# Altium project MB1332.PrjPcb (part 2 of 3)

## Sheet Peripherals.SchDoc: Peripherals
size A4; Date: Not used; ApprovedBy: Not used; CheckedBy: Not used; Author: Not used; CompanyName: STMicroelectronics; DrawnBy: Not used; Engineer: Not used; Organization: Not used; Address1: Not used; Address2: Not used; Address3: Not used; Address4: Not used; DocumentNumber: Not used; Revision: Not used; SheetNumber: 13; SheetTotal: 17
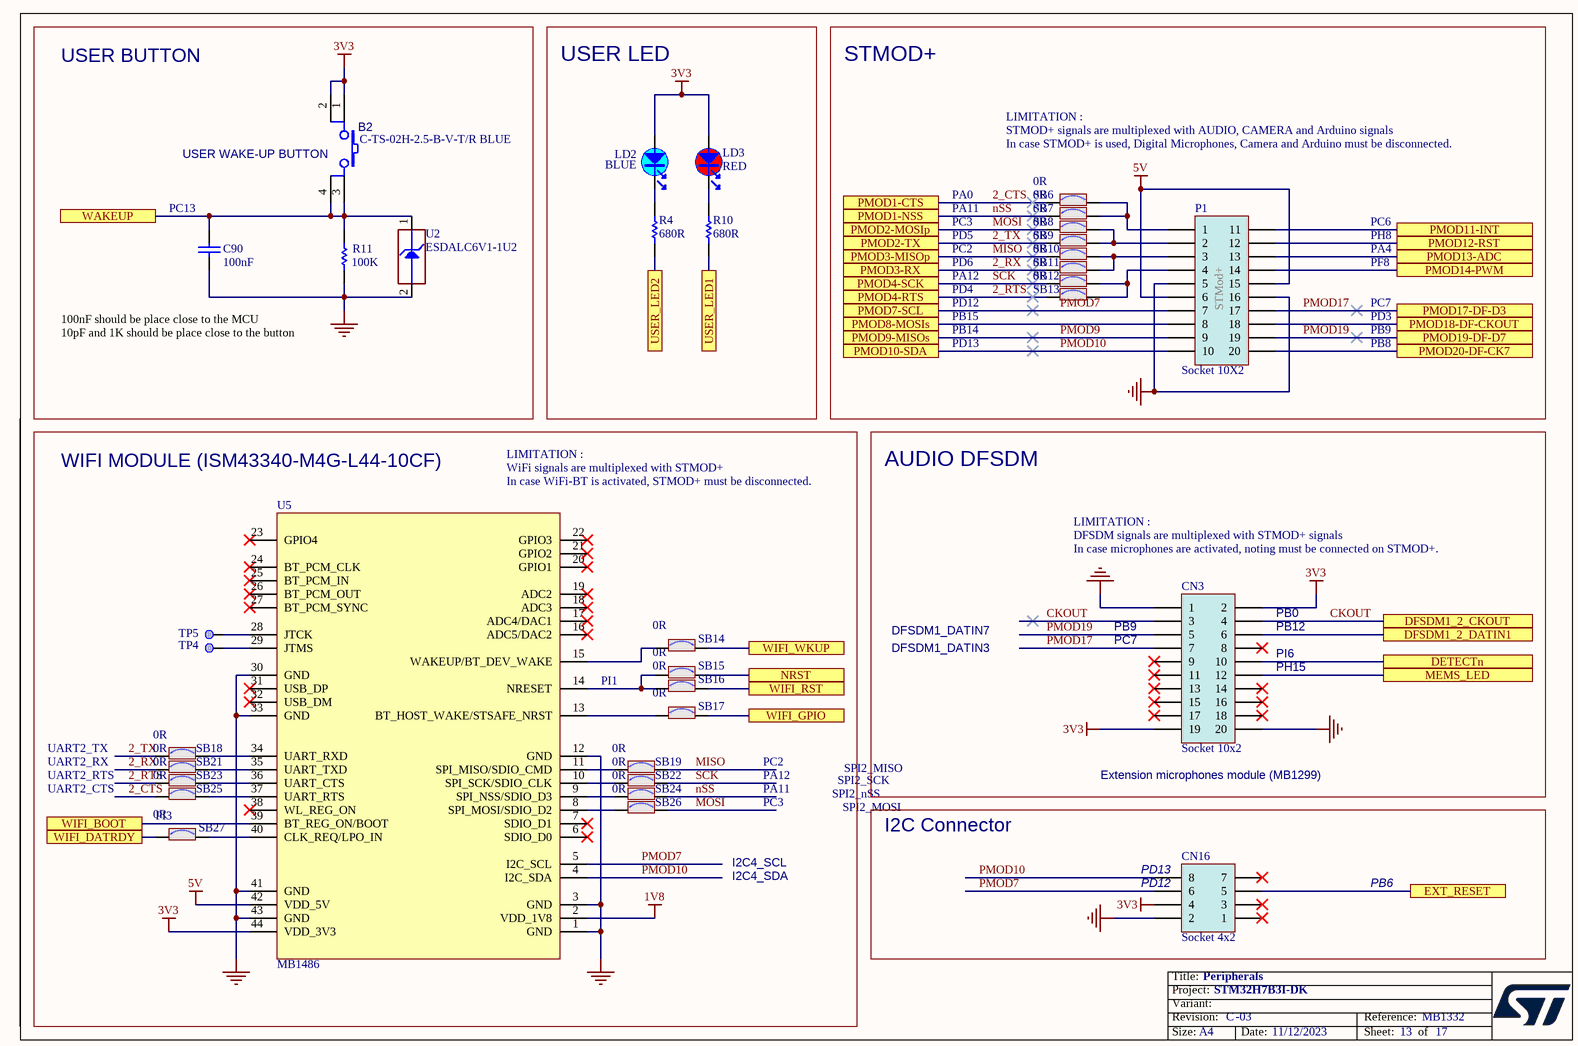
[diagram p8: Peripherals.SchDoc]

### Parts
B2  value C-TS-02H-2.5-B-V-T/R BLUE  [SWI_JIUBABA_C-TS-02H-2-5-B-V-T_R_BLUE]  (hidden comment: SW-PUSH-TS-02H-Blue)
C90  value 100nF  [C0402]  (hidden comment: Capacitor)
CN3  Socket 10x2  [CON_FCI_20021311-XXX20XXLF]
CN16  Socket 4x2  [CON_SAMTEC_SSM-104-L-DH]
LD2  value BLUE  [LED_0603_OSRAM_LB-Q39G-L2OO-35-1_BLUE_1A2K_H0P4]  (hidden comment: LED_blue)
LD3  value RED  [LED_0603_VISHAY_VLMS1300-GS08_RED_1A2K_H0P8]  (hidden comment: LED_red)
P1  value Socket 10X2  [CON_SAMTEC_SQT-110-01-F-D-RA__STMOD+]  (hidden comment: Socket 10X2 STMod+)
R4  value 680R  [R0603]  (hidden comment: Resistor)
R10  value 680R  [R0603]  (hidden comment: Resistor)
R11  value 100K  [R0402]  (hidden comment: Resistor)
SB6  value 0R  [SOLDER-BRIDGE_R0603-0R]  (hidden comment: SB_ON)
SB7  value 0R  [SOLDER-BRIDGE_R0603-0R]  (hidden comment: SB_ON)
SB8  value 0R  [SOLDER-BRIDGE_R0603-0R]  (hidden comment: SB_ON)
SB9  value 0R  [SOLDER-BRIDGE_R0603-0R]  (hidden comment: SB_ON)
SB10  value 0R  [SOLDER-BRIDGE_R0603-0R]  (hidden comment: SB_ON)
SB11  value 0R  [SOLDER-BRIDGE_R0603-0R]  (hidden comment: SB_ON)
SB12  value 0R  [SOLDER-BRIDGE_R0603-0R]  (hidden comment: SB_ON)
SB13  value 0R  [SOLDER-BRIDGE_R0603-0R]  (hidden comment: SB_ON)
SB14  value 0R  [SOLDER-BRIDGE_R0603-0R]  (hidden comment: SB_ON)
SB15  value 0R  [SOLDER-BRIDGE_R0603-0R]  (hidden comment: SB_ON)
SB16  value 0R  [SOLDER-BRIDGE_R0603-0R]  (hidden comment: SB_ON)
SB17  value 0R  [SOLDER-BRIDGE_R0603-0R]  (hidden comment: SB_ON)
SB18  value 0R  [SOLDER-BRIDGE_R0603-0R]  (hidden comment: SB_ON)
SB19  value 0R  [SOLDER-BRIDGE_R0603-0R]  (hidden comment: SB_ON)
SB21  value 0R  [SOLDER-BRIDGE_R0603-0R]  (hidden comment: SB_ON)
SB22  value 0R  [SOLDER-BRIDGE_R0603-0R]  (hidden comment: SB_ON)
SB23  value 0R  [SOLDER-BRIDGE_R0603-0R]  (hidden comment: SB_ON)
SB24  value 0R  [SOLDER-BRIDGE_R0603-0R]  (hidden comment: SB_ON)
SB25  value 0R  [SOLDER-BRIDGE_R0603-0R]  (hidden comment: SB_ON)
SB26  value 0R  [SOLDER-BRIDGE_R0603-0R]  (hidden comment: SB_ON)
SB27  value 0R  [SOLDER-BRIDGE_R0603-0R]  (hidden comment: SB_ON)
TP4  Test Point  [TP_SMD_0-6MM]  (value not drawn)  (no BOM)
TP5  Test Point  [TP_SMD_0-6MM]  (value not drawn)  (no BOM)
U2  value ESDALC6V1-1U2  [ESD_ST0201]  (hidden comment: ESD-TRANSIL)
U5  value MB1486  [MOD_WIFI_INVENTEK_ISM43362]  (hidden comment: WIFI MODULE INTERPOSER)

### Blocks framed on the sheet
USER BUTTON: B2 C90 R11 U2
USER LED: LD2 LD3 R4 R10
STMOD+: P1 SB6-SB13
WIFI MODULE (ISM43340-M4G-L44-10CF): SB14-SB19 SB21-SB27 TP4 TP5 U5
AUDIO DFSDM: CN3
I2C Connector: CN16

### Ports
DETECTn, DFSDM1_2_CKOUT, DFSDM1_2_DATIN1, EXT_RESET, MEMS_LED, NRST, PMOD1-CTS, PMOD1-NSS, PMOD2-MOSIp, PMOD2-TX, PMOD3-MISOp, PMOD3-RX, PMOD4-RTS, PMOD4-SCK, PMOD7-SCL, PMOD8-MOSIs, PMOD9-MISOs, PMOD10-SDA, PMOD11-INT, PMOD12-RST, PMOD13-ADC, PMOD14-PWM, PMOD17-DF-D3, PMOD18-DF-CKOUT, PMOD19-DF-D7, PMOD20-DF-CK7, USER_LED1, USER_LED2, WAKEUP, WIFI_BOOT, WIFI_DATRDY, WIFI_GPIO, WIFI_RST, WIFI_WKUP

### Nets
1V8: U5.2(VDD_1V8)
3V3: B2.1 B2.2 CN3.2 CN3.19 CN16.4 LD2.1 LD3.1 U5.44(VDD_3V3)
5V: P1.6 P1.15 U5.42(VDD_5V)
GND: C90.1 CN3.1 CN3.20 CN16.2 P1.5 P1.16 R11.1 U2.2(GND) U5.1(GND) U5.3(GND) U5.12(GND) U5.30(GND) U5.33(GND) U5.41(GND) U5.43(GND)
2_CTS: SB6.1 SB25.2 ; port PMOD1-CTS
2_RTS: SB13.1 SB23.2 ; port PMOD4-RTS
2_RX: SB11.1 SB21.2 ; port PMOD3-RX
2_TX: SB9.1 SB18.2 ; port PMOD2-TX
CKOUT: CN3.3 CN3.4 ; port DFSDM1_2_CKOUT
DCMI_D0: P1.11 ; port PMOD11-INT
DCMI_D5: P1.18 ; port PMOD18-DF-CKOUT
DCMI_D6: P1.20 ; port PMOD20-DF-CK7
DETECTn: CN3.10 ; port DETECTn
DFSDM1_2_DATIN1: CN3.6 ; port DFSDM1_2_DATIN1
EXT_RESET: CN16.5 ; port EXT_RESET
MEMS_LED: CN3.12 ; port MEMS_LED
MISO: SB10.1 SB19.1 ; port PMOD3-MISOp
MOSI: SB8.1 SB26.1 ; port PMOD2-MOSIp
nSS: SB7.1 SB24.1 ; port PMOD1-NSS
PH8: P1.12 ; port PMOD12-RST
PMOD7: CN16.6 P1.7 U5.5(I2C_SCL) ; port PMOD7-SCL
PMOD8-MOSIs: P1.8 ; port PMOD8-MOSIs
PMOD9: P1.9 ; port PMOD9-MISOs
PMOD10: CN16.8 P1.10 U5.4(I2C_SDA) ; port PMOD10-SDA
PMOD13-ADC: P1.13 ; port PMOD13-ADC
PMOD14-PWM: P1.14 ; port PMOD14-PWM
PMOD17: CN3.7 P1.17 ; port PMOD17-DF-D3  [project net DCMI_D1]
PMOD19: CN3.5 P1.19 ; port PMOD19-DF-D7  [project net DCMI_D7]
SCK: SB12.1 SB22.1 ; port PMOD4-SCK  [project net PA12]
T_NRST: SB15.2 ; port NRST
USER_LED1: R10.2 ; port USER_LED1
USER_LED2: R4.2 ; port USER_LED2
WAKEUP: B2.3 B2.4 C90.2 R11.2 U2.1(IO1) ; port WAKEUP
WIFI_BOOT: U5.39(BT_REG_ON/BOOT) ; port WIFI_BOOT
WIFI_DATRDY: SB27.1 ; port WIFI_DATRDY
WIFI_GPIO: SB17.2 ; port WIFI_GPIO
WIFI_RST: SB16.2 ; port WIFI_RST
WIFI_WKUP: SB14.2 ; port WIFI_WKUP
NetLD2_2: LD2.2 R4.1
NetLD3_2: LD3.2 R10.1
NetP1_1: P1.1 SB6.2 SB7.2
NetP1_2: P1.2 SB8.2 SB9.2
NetP1_3: P1.3 SB10.2 SB11.2
NetP1_4: P1.4 SB12.2 SB13.2
NetSB14_1: SB14.1 U5.15(WAKEUP/BT_DEV_WAKE)
NetSB15_1: SB15.1 SB16.1 U5.14(NRESET)
NetSB17_1: SB17.1 U5.13(BT_HOST_WAKE/STSAFE_NRST)
NetSB18_1: SB18.1 U5.34(UART_RXD)
NetSB19_2: SB19.2 U5.11(SPI_MISO/SDIO_CMD)
NetSB21_1: SB21.1 U5.35(UART_TXD)
NetSB22_2: SB22.2 U5.10(SPI_SCK/SDIO_CLK)
NetSB23_1: SB23.1 U5.36(UART_CTS)
NetSB24_2: SB24.2 U5.9(SPI_NSS/SDIO_D3)
NetSB25_1: SB25.1 U5.37(UART_RTS)
NetSB26_2: SB26.2 U5.8(SPI_MOSI/SDIO_D2)
NetSB27_2: SB27.2 U5.40(CLK_REQ/LPO_IN)
NetTP4_1: TP4.1 U5.29(JTMS)
NetTP5_1: TP5.1 U5.28(JTCK)

Not connected (* = marked no-connect by the designer): CN3 8* 9* 11* 13* 14* 15* 16* 17* 18*; CN16 1* 3* 7*; U5 6(SDIO_D0)* 7(SDIO_D1)* 16(ADC5/DAC2)* 17(ADC4/DAC1)* 18(ADC3)* 19(ADC2)* 20(GPIO1)* 21(GPIO2)* 22(GPIO3)* 23(GPIO4)* 24(BT_PCM_CLK)* 25(BT_PCM_IN)* 26(BT_PCM_OUT)* 27(BT_PCM_SYNC)* 31(USB_DP)* 32(USB_DM)* 38(WL_REG_ON)*

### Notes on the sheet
- (near B2) USER WAKE-UP BUTTON
- LIMITATION :
  STMOD+ signals are multiplexed with AUDIO, CAMERA and Arduino signals
  In case STMOD+ is used, Digital Microphones, Camera and Arduino must be disconnected.
- (near C90) PC13
- PA0
- PC3
- PD5
- PC2
- PA11
- PC6
- PH8
- PA4
- PD6
- PA12
- PD12
- PB15
- PD4
- PF8
- PC7
- PD3
- 100nF should be place close to the MCU
  10pF and 1K should be place close to the button
- PD13
- PB14
- PB9
- PB8
- LIMITATION :
  WiFi signals are multiplexed with STMOD+
  In case WiFi-BT is activated, STMOD+ must be disconnected.
- DFSDM1_DATIN3
- DFSDM1_DATIN7
- (near CN3) LIMITATION :
  DFSDM signals are multiplexed with STMOD+ signals
  In case microphones are activated, noting must be connected on STMOD+.
- (near CN3) PB9
- (near CN3) PC7
- (near CN3) PB0
- (near CN3) PB12
- (near CN3) PI6
- PI1
- (near CN3) PH15
- UART2_TX
- UART2_RX
- UART2_RTS
- UART2_CTS
- SPI2_nSS
- SPI2_SCK
- SPI2_MISO
- (near CN3) Extension microphones module (MB1299)
- PI3
- SPI2_MOSI
- I2C4_SCL
- I2C4_SDA
- (near CN16) PD13
- (near CN16) PD12
- PB6

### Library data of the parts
B2 = MCD-00172: Switch HW SMD blue; Part_Type: Misc; Manufacturer: JIUBABA; Part_Preference: Alternate; Provided_By: SUBCO; Alternate_EMS: A; Component_Country_Of_Origin: Unknown; ID: 2697; ShowFields: YES
C90 = MCD-00006: Capacitor, MLCC, 100nF, 16V, X7R, +/-10%, 0402, T=0.5mm; Manufacturer_Part_Number: CC0402KRX7R7BB104; Manufacturer: YAGEO; Part_Preference: Recommended; Partial_Alternate_Internal_Part_Number: MCD-03299; Component_Country_Of_Origin: China; ID: 2474; Order_Code_RS: 9402047; ShowFields: YES
CN3 = MCD-00147: Socket for MB1299, 10x2, 1.27mm, VR, TH, Height 4.30mm/2.40mm; Part_Type: Connector; Manufacturer_Part_Number: 20021311-00020T4LF; Manufacturer: AMPHENOL ICC; Alternate_Manufacturer_Part_Number: 234220S1410; Alternate_Manufacturer: JIUBABA; Part_Preference: Recommended; Partial_Alternate_Internal_Part_Number: MCD-03007; Provided_By: SUBCO; Component_Country_Of_Origin: China; ID: 2719; Order_Code_RS: 170-8859; ShowFields: YES
CN16 = MCD-00131: Socket, 4x2, 2.54mm, RA, SMT, Height 5.72mm; Manufacturer_Part_Number: SSM-104-L-DH; Manufacturer: SAMTEC; Part_Type: Connector; Alternate_Manufacturer_Part_Number: F206A-2x04MGF-LA; Alternate_Manufacturer: JIUBABA; Part_Preference: Recommended; Provided_By: SUBCO; Component_Country_Of_Origin: China, Costa Rica, Malaysia, United States, Vietnam; ID: 2740; Order_Code_RS: 198-1510; ShowFields: YES
LD2 = MCD-00585: LED Blue, 0603 SMD, Forward Voltage Min=2,8V, Max=3,8V; Manufacturer_Part_Number: LB Q39G-L2OO-35-1; Manufacturer: OSRAM OPTO SEMICONDUCTORS; Part_Type: Display; Alternate_Manufacturer_Part_Number: 19-217-BHC-ZL1M2RY-3T-V4; Alternate_Manufacturer: EVERLIGHT; Full_Alternate_Internal_Part_Number: MCD-02398; Part_Preference: Recommended; Order_Code_RS: 9148643; Provided_By: SUBCO; Component_Country_Of_Origin: Unknown; ID: 3159; ShowFields: YES
LD3 = MCD-00587: LED Red, 0603 SMD, 2V Forward Voltage; Manufacturer_Part_Number: VLMS1300-GS08; Manufacturer: VISHAY; Alternate_Manufacturer_Part_Number: LS Q976-NR-1; Alternate_Manufacturer: OSRAM OPTO SEMICONDUCTORS; Part_Type: Display; Full_Alternate_Internal_Part_Number: MCD-02401; Part_Preference: Recommended; Provided_By: SUBCO; Component_Country_Of_Origin: China; ID: 3154; ShowFields: YES
P1 = MCD-00309: Socket 10x2, 2.00mm, RA, TH, Height 6.35mm/2.29mm; Part_Type: Connector; Manufacturer_Part_Number: SQT-110-01-F-D-RA; Manufacturer: SAMTEC; Alternate_Manufacturer_Part_Number: FH200020C-12300; Alternate_Manufacturer: JIUBABA; Part_Preference: Recommended; Provided_By: SUBCO; Component_Country_Of_Origin: China, Costa Rica, Malaysia, United States, Vietnam; ID: 2557; Order_Code_RS: 180-1541; ShowFields: YES
R4 R10 = MCD-00508: Resistor,680R,0603,1%,1/10W; Manufacturer_Part_Number: RC0603FR-07680RL; Manufacturer: YAGEO; Part_Preference: Recommended; Provided_By: SUBCO; Component_Country_Of_Origin: China; ID: 3235; ShowFields: YES
R11 = MCD-00059: Resistor,100K,0402,1%,1/16W; Manufacturer_Part_Number: RC0402FR-07100KL; Manufacturer: YAGEO; Alternate_Manufacturer_Part_Number: RT0402FRE07100KL; Part_Preference: Recommended; Partial_Alternate_Internal_Part_Number: MCD-03301; Provided_By: SUBCO; Component_Country_Of_Origin: China; ID: 2533; Order_Code_RS: 2421891; ShowFields: YES
SB6-SB19 SB21-SB27 = MCD-00071: Solder Bridge ON; Part_Type: Resistor; Manufacturer_Part_Number: RC0603JR-070RL; Manufacturer: YAGEO; Manufacturer_HQ_COO: Unknown; Part_Preference: Recommended; Provided_By: SUBCO; Component_Country_Of_Origin: China; ID: 2521; Order_Code_RS: 199-5647; ShowFields: YES
TP4 TP5 = MCD-00631: Test Point 0.6mm; Part_Type: Misc; Part_Preference: Recommended; ID: 3108; ShowFields: YES
U2 = MCD-00170: ESD protection 6V1; Part_Type: Diode; Manufacturer: STMICROELECTRONICS; BMS_Part_Number: 9151132; Manufacturer_HQ_COO: EU; Part_Preference: Recommended; Provided_By: SUBCO with ST control; Component_Country_Of_Origin: China; ID: 2696; Order_Code_RS: 795-8404; ShowFields: YES
U5 = MCD-01999: 44 pins Interposer for WIFI module (MB1486 module is with INVENTEK ISM43340-M4G-L44-10CF); Part_Type: Misc; Manufacturer_Part_Number: MB1486 - WIFI MODULE WITH INVENTEK ISM43340-M4G-L44-10CF; Manufacturer: STMICROELECTRONICS; Manufacturer_HQ_COO: EU; Part_Preference: Recommended; ECCN_US: 5A992C; Provided_By: SUBCO with ST control; Component_Country_Of_Origin: Unknown; ID: 4099; ShowFields: YES

## Sheet SDcard.SchDoc: SD Card
size A4; Date: Not used; ApprovedBy: Not used; CheckedBy: Not used; Author: Not used; CompanyName: STMicroelectronics; DrawnBy: Not used; Engineer: Not used; Organization: Not used; Address1: Not used; Address2: Not used; Address3: Not used; Address4: Not used; DocumentNumber: Not used; Revision: Not used; SheetNumber: 7; SheetTotal: 17
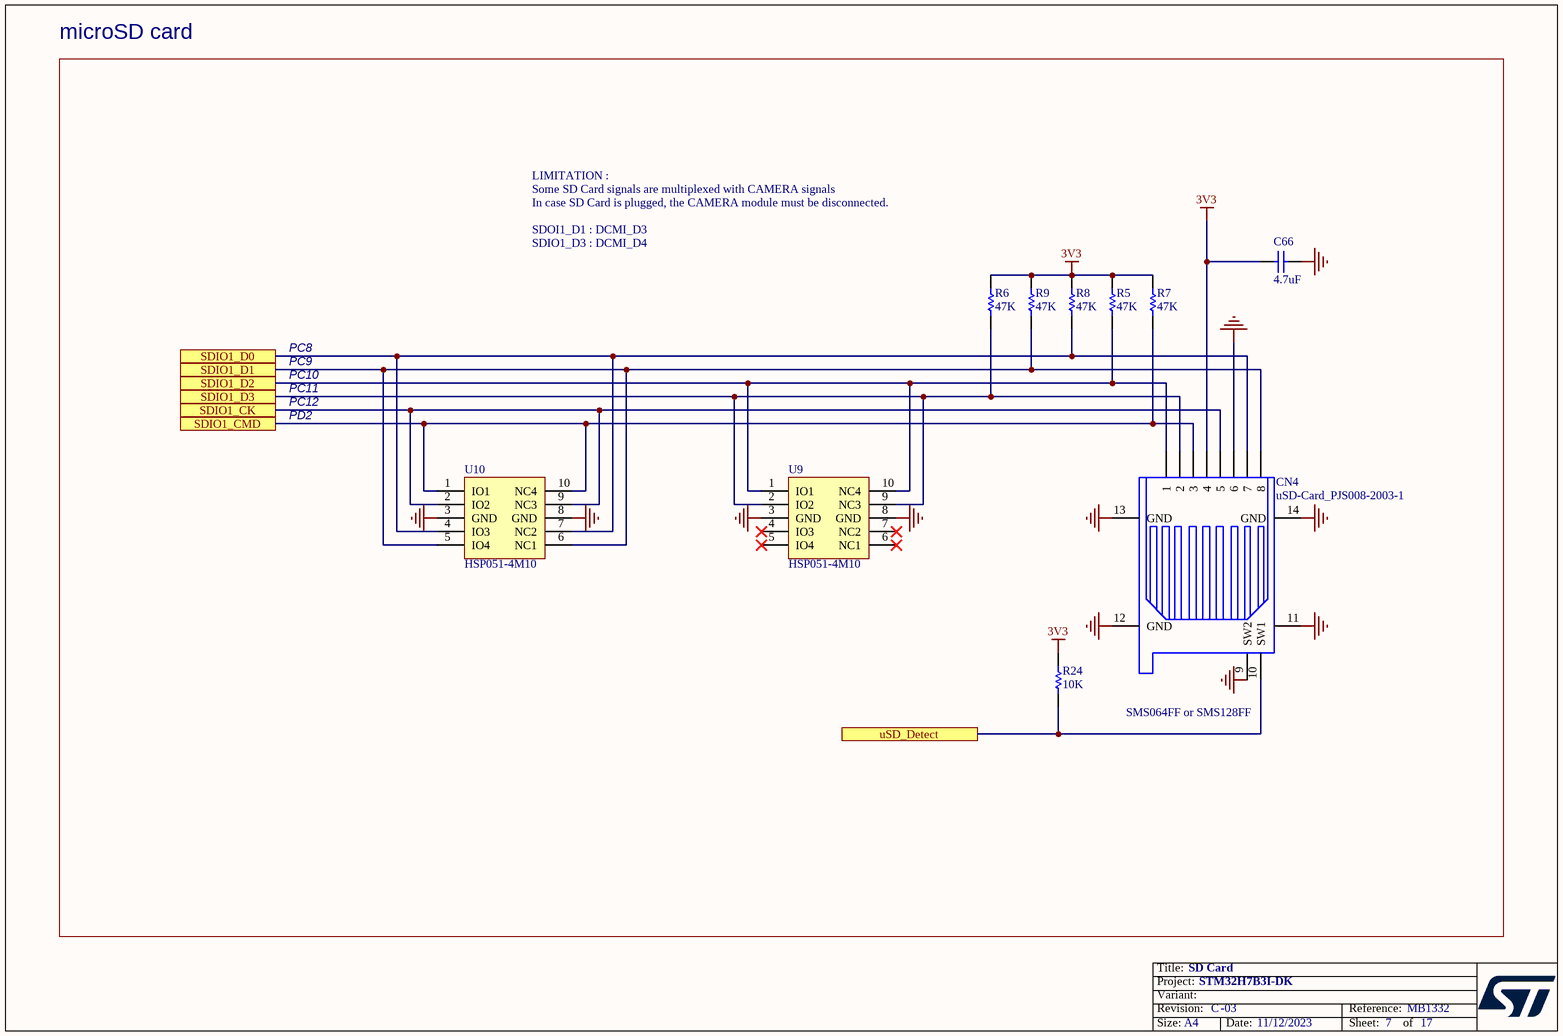
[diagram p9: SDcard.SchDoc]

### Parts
C66  value 4.7uF  [C0603_H0P8]  (hidden comment: Capacitor)
CN4  value uSD-Card_PJS008-2003-1  [CON_MICROSD_YAMAICHI_PJS008-2003-1]  (hidden comment: microSD-PJS008-2003)
R5  value 47K  [R0402]  (hidden comment: Resistor)
R6  value 47K  [R0402]  (hidden comment: Resistor)
R7  value 47K  [R0402]  (hidden comment: Resistor)
R8  value 47K  [R0402]  (hidden comment: Resistor)
R9  value 47K  [R0402]  (hidden comment: Resistor)
R24  value 10K  [R0603]  (hidden comment: Resistor)
U9  HSP051-4M10  [ESD_UQFN-10L_2P5X1_P050]
U10  HSP051-4M10  [ESD_UQFN-10L_2P5X1_P050]

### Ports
SDIO1_CK, SDIO1_CMD, SDIO1_D0, SDIO1_D1, SDIO1_D2, SDIO1_D3, uSD_Detect

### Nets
3V3: C66.1 CN4.4 R5.2 R6.2 R7.2 R8.2 R9.2 R24.2
GND: C66.2 CN4.6 CN4.9(SW2) CN4.11(GND) CN4.12(GND) CN4.13(GND) CN4.14(GND) U9.3(GND) U9.8(GND) U10.3(GND) U10.8(GND)
DCMI_D3: CN4.8 R9.1 U10.5(IO4) U10.6(NC1) ; port SDIO1_D1
DCMI_D4: CN4.2 R6.1 U9.2(IO2) U9.9(NC3) ; port SDIO1_D3
SDIO1_CK: CN4.5 U10.2(IO2) U10.9(NC3) ; port SDIO1_CK
SDIO1_CMD: CN4.3 R7.1 U10.1(IO1) U10.10(NC4) ; port SDIO1_CMD
SDIO1_D0: CN4.7 R8.1 U10.4(IO3) U10.7(NC2) ; port SDIO1_D0
SDIO1_D2: CN4.1 R5.1 U9.1(IO1) U9.10(NC4) ; port SDIO1_D2
uSD_Detect: CN4.10(SW1) R24.1 ; port uSD_Detect

Not connected (* = marked no-connect by the designer): U9 4(IO3)* 5(IO4)* 6(NC1)* 7(NC2)*

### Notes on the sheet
- microSD card
- LIMITATION :
  Some SD Card signals are multiplexed with CAMERA signals
  In case SD Card is plugged, the CAMERA module must be disconnected.
  SDOI1_D1 : DCMI_D3
  SDIO1_D3 : DCMI_D4
- PC8
- PC9
- PC10
- PC11
- PD2
- PC12
- SMS064FF or SMS128FF

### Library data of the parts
C66 = MCD-01721: Capacitor, 4.7uF, 10V, X5R, 10%, 0603, T=0.8mm; Manufacturer_Part_Number: CC0603KRX5R6BB475; Manufacturer: YAGEO; Part_Preference: Recommended; Provided_By: SUBCO; Component_Country_Of_Origin: China; ID: 3821; ShowFields: YES
CN4 = MCD-00023: MicroSD Card Conn, Reversed-Type, Mnt Push-Push, Positionning holes; Manufacturer_Part_Number: PJS008-2003-1; Manufacturer: YAMAICHI; Part_Type: Connector; Part_Preference: Recommended; Provided_By: SUBCO; Component_Country_Of_Origin: Unknown; ID: 2492; ShowFields: YES
R5-R9 = MCD-00063: Resistor,47K,0402,1%,1/16W; Manufacturer_Part_Number: RC0402FR-0747KL; Manufacturer: YAGEO; Part_Preference: Recommended; Provided_By: SUBCO; Component_Country_Of_Origin: China; ID: 2528; Order_Code_RS: 9239430; ShowFields: YES
R24 = MCD-00220: Resistor,10K,0603,1%,1/10W; Manufacturer_Part_Number: RC0603FR-0710KL; Manufacturer: YAGEO; Part_Preference: Recommended; Provided_By: SUBCO; Component_Country_Of_Origin: China; ID: 2649; ShowFields: YES
U9 U10 = MCD-00667: 4-line ESD protection for high speed lines; Part_Type: Diode; Manufacturer: STMICROELECTRONICS; BMS_Part_Number: 9179041; Manufacturer_HQ_COO: EU; Part_Preference: Recommended; Provided_By: SUBCO with ST control; Component_Country_Of_Origin: Philippines; ID: 3081; ShowFields: YES

## Sheet USB_OTG_HS_externalPHY.SchDoc: USB OTG HS with external PHY
size A3; Date: Not used; ApprovedBy: Not used; CheckedBy: Not used; Author: Not used; CompanyName: STMicroelectronics; DrawnBy: Not used; Engineer: Not used; Organization: Not used; Address1: Not used; Address2: Not used; Address3: Not used; Address4: Not used; DocumentNumber: Not used; Revision: Not used; SheetNumber: 4; SheetTotal: 17
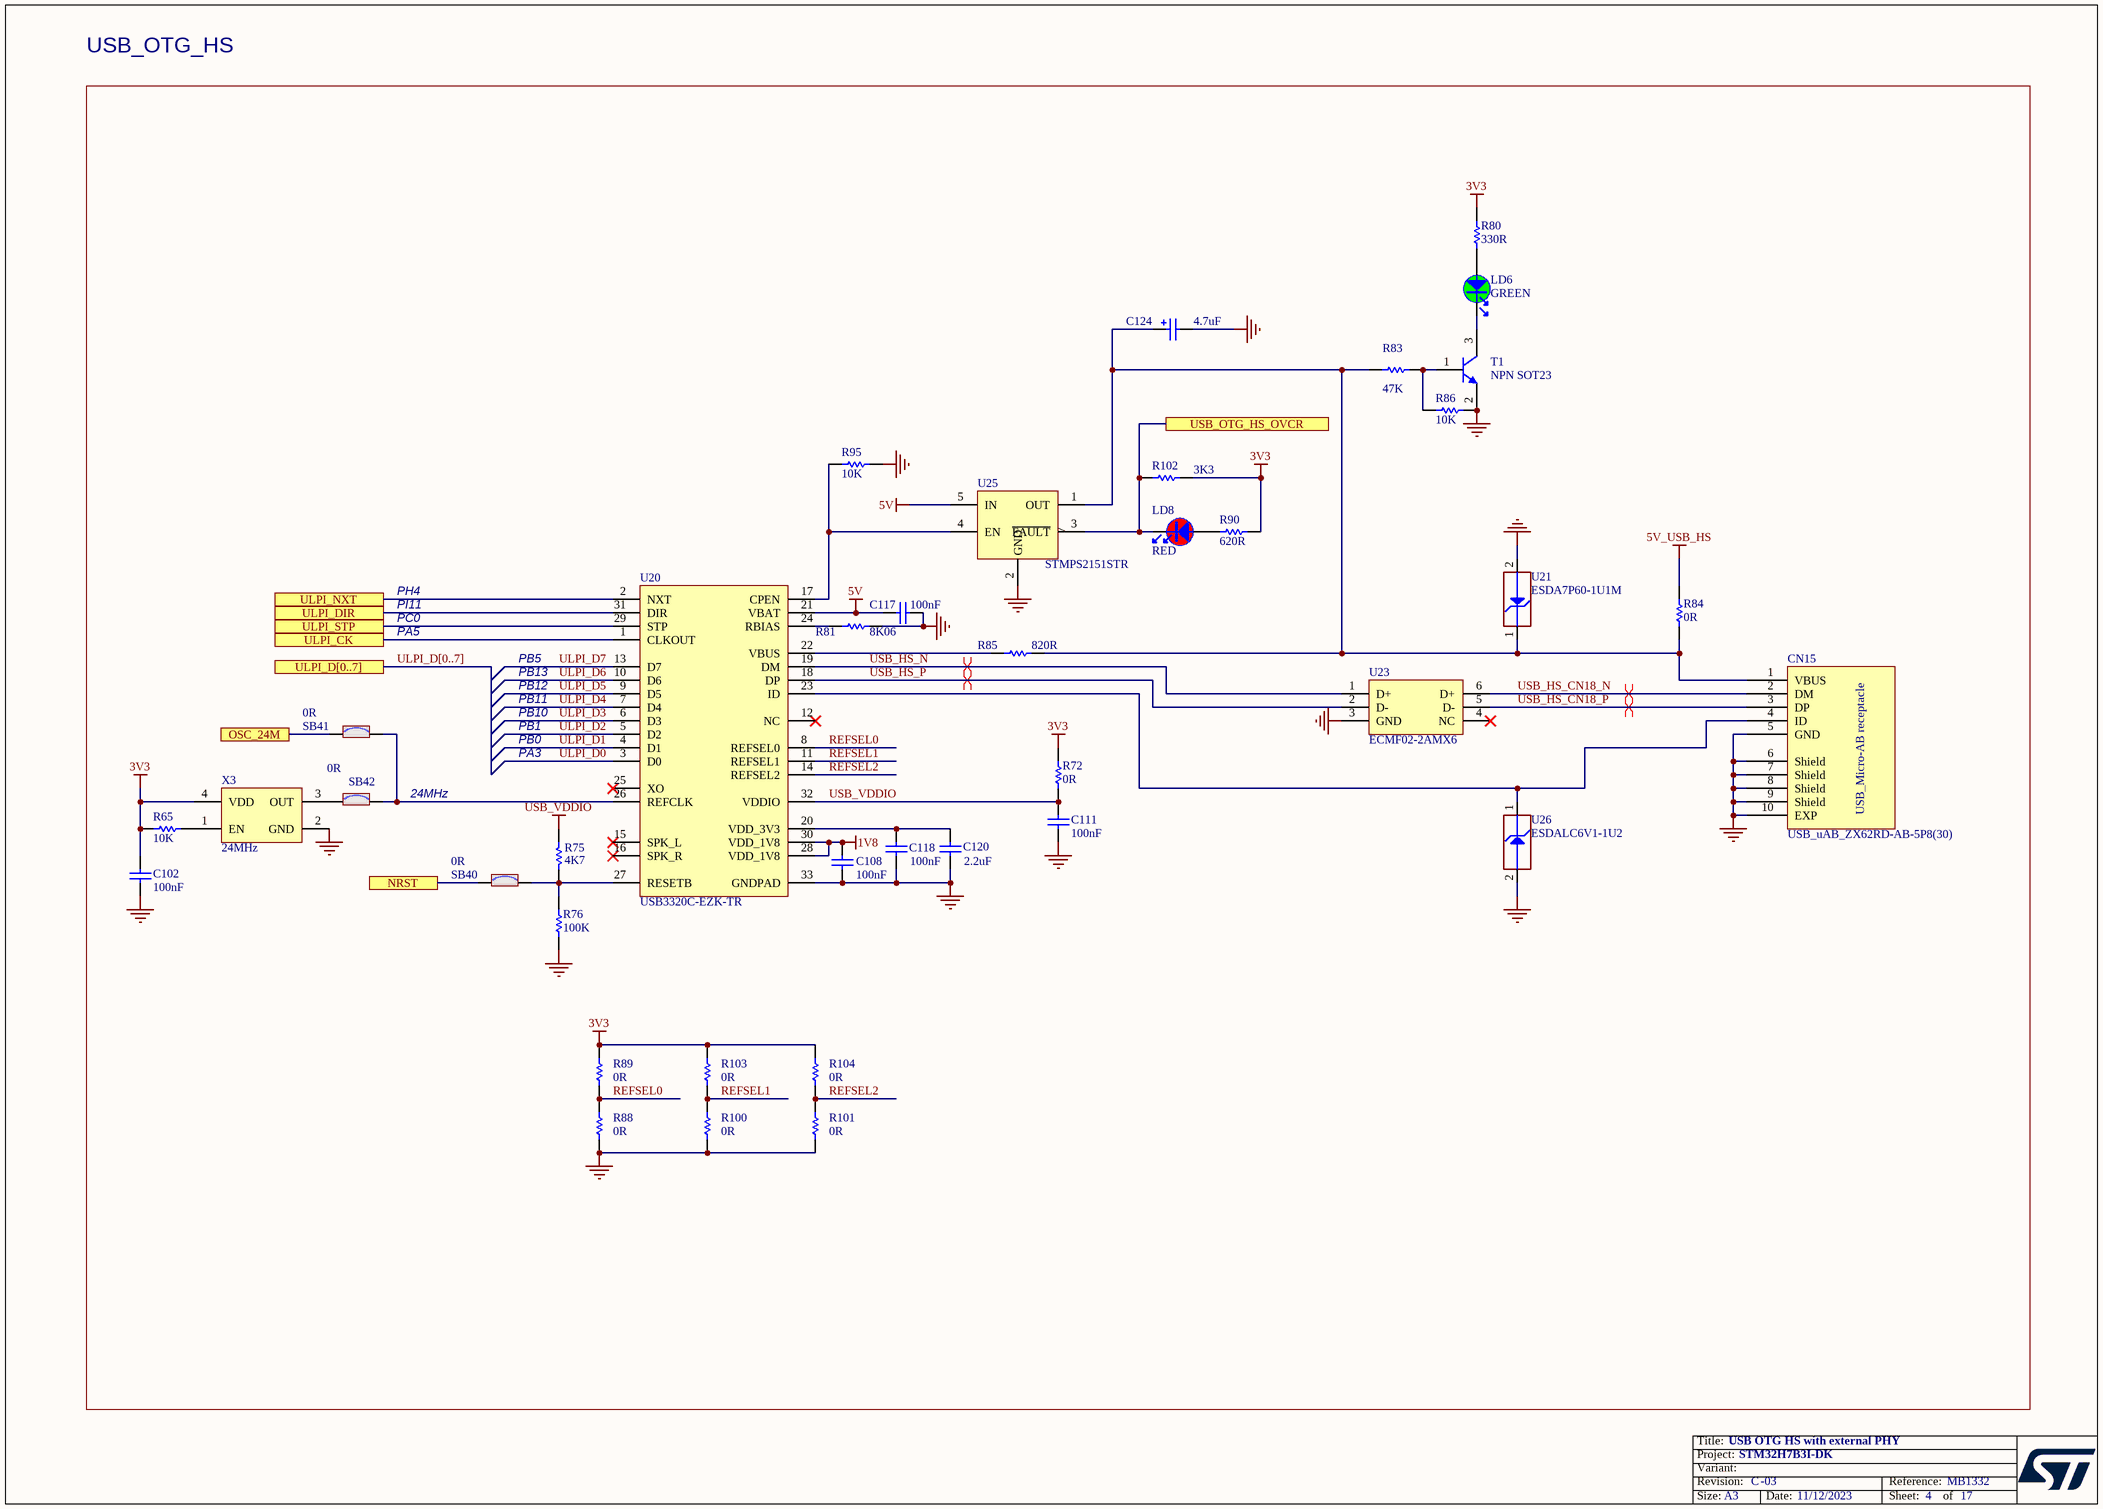
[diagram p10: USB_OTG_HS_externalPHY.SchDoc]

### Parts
C102  value 100nF  [C0402]  (hidden comment: Capacitor)
C108  value 100nF  [C0402]  (hidden comment: Capacitor)
C111  value 100nF  [C0402]  (hidden comment: Capacitor)
C117  value 100nF  [C0402]  (hidden comment: Capacitor)
C118  value 100nF  [C0402]  (hidden comment: Capacitor)
C120  value 2.2uF  [C0603]  (hidden comment: Capacitor)
C124  value 4.7uF  [CPOL_TAJ-A_1206_H180]  (hidden comment: Cap_POL_TANA)
CN15  value USB_uAB_ZX62RD-AB-5P8(30)  [CON_USBMICROAB_MOLEX_47590-0001_H3]  (hidden comment: USB_uAB_47590.0001)
LD6  value GREEN  [LED_0603_OSRAM_LG-Q396-PS-35_GREEN_1A2K_H0P4]  (hidden comment: LED_green)
LD8  value RED  [LED_0603_VISHAY_VLMS1300-GS08_RED_1A2K_H0P8]  (hidden comment: LED_red)
R65  value 10K  [R0402]  (hidden comment: Resistor)
R72  value 0R  [R0603]  (hidden comment: Resistor)
R75  value 4K7  [R0402]  (hidden comment: Resistor)
R76  value 100K  [R0402]  (hidden comment: Resistor)
R80  value 330R  [R0603]  (hidden comment: Resistor)
R81  value 8K06  [R0603]  (hidden comment: Resistor)
R83  value 47K  [R0402]  (hidden comment: Resistor)
R84  value 0R  [R0805]  (hidden comment: Resistor)
R85  value 820R  [R0603]  (hidden comment: Resistor)
R86  value 10K  [R0402]  (hidden comment: Resistor)
R88  value 0R  [R0603]  (hidden comment: Resistor)
R89  value 0R  [R0603]  (hidden comment: Resistor)
R90  value 620R  [R0603]  (hidden comment: Resistor)
R95  value 10K  [R0402]  (hidden comment: Resistor)
R100  value 0R  [R0603]  (hidden comment: Resistor)
R101  value 0R  [R0603]  (hidden comment: Resistor)
R102  value 3K3  [R0402]  (hidden comment: Resistor)
R103  value 0R  [R0603]  (hidden comment: Resistor)
R104  value 0R  [R0603]  (hidden comment: Resistor)
SB40  value 0R  [SOLDER-BRIDGE_R0603-0R]  (hidden comment: SB_ON)
SB41  value 0R  [SOLDER-BRIDGE_R0603-0R]  (hidden comment: SB_ON)
SB42  value 0R  [SOLDER-BRIDGE_R0603-0R]  (hidden comment: SB_ON)
T1  value NPN SOT23  [NPN_SOT23]  (hidden comment: 9013-SOT23)
U20  value USB3320C-EZK-TR  [ICC_QFN32-EPAD_5X5_P050]  (hidden comment: USB3320C-EZK)
U21  value ESDA7P60-1U1M  [ESD_QFN2_1P6X1_P125]  (hidden comment: ESD-TRANSIL)
U23  ECMF02-2AMX6  [ESD_QFN-6L_1P7X1P5_P050]
U25  STMPS2151STR  [MOS_SOT23-5L]
U26  value ESDALC6V1-1U2  [ESD_ST0201]  (hidden comment: ESD-TRANSIL)
X3  value 24MHz  [OSC_NDK_NZ2520SB_4P]  (hidden comment: OSCILLATOR_4_PINS)

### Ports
NRST, OSC_24M, ULPI_CK, ULPI_D[0..7], ULPI_DIR, ULPI_NXT, ULPI_STP, USB_OTG_HS_OVCR

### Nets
1V8: C108.1 U20.28(VDD_1V8) U20.30(VDD_1V8)
3V3: C102.2 R65.1 R72.1 R80.2 R89.2 R90.2 R102.2 R103.2 R104.2 X3.4(VDD)
5V: C117.1 U20.21(VBAT) U25.5(IN)
5V_USB_HS: R84.2
GND: C102.1 C108.2 C111.2 C117.2 C118.2 C120.1 C124.2 CN15.5(GND) CN15.6(Shield) CN15.7(Shield) CN15.8(Shield) CN15.9(Shield) CN15.10(EXP) R76.1 R81.2 R86.2 R88.1 R95.2 R100.1 R101.1 T1.2(E) U20.33(GNDPAD) U21.2(GND) U23.3(GND) U25.2(GND) U26.2(GND) X3.2(GND)
USB_VDDIO: C111.1 R72.2 R75.2 U20.32(VDDIO)
OSC_24M: SB41.2 ; port OSC_24M
REFSEL0: R88.2 R89.1 U20.8(REFSEL0)
REFSEL1: R100.2 R103.1 U20.11(REFSEL1)
REFSEL2: R101.2 R104.1 U20.14(REFSEL2)
T_NRST: SB40.2 ; port NRST
ULPI_CK: U20.1(CLKOUT) ; port ULPI_CK
ULPI_D0: U20.3(D0)
ULPI_D1: U20.4(D1)
ULPI_D2: U20.5(D2)
ULPI_D3: U20.6(D3)
ULPI_D4: U20.7(D4)
ULPI_D5: U20.9(D5)
ULPI_D6: U20.10(D6)
ULPI_D7: U20.13(D7)
ULPI_DIR: U20.31(DIR) ; port ULPI_DIR
ULPI_NXT: U20.2(NXT) ; port ULPI_NXT
ULPI_STP: U20.29(STP) ; port ULPI_STP
USB_HS_CN18_N: CN15.2(DM) U23.6(D+)
USB_HS_CN18_P: CN15.3(DP) U23.5(D-)
USB_HS_N: U20.19(DM) U23.1(D+)
USB_HS_P: U20.18(DP) U23.2(D-)
USB_OTG_HS_OVCR: LD8.2 R102.1 U25.3(~{FAULT}) ; port USB_OTG_HS_OVCR
NetC118_1: C118.1 C120.2 U20.20(VDD_3V3)
NetC124_1: C124.1 CN15.1(VBUS) R83.1 R84.1 R85.2 U21.1(IO1) U25.1(OUT)
NetCN15_4: CN15.4(ID) U20.23(ID) U26.1(IO1)
NetLD6_1: LD6.1 R80.1
NetLD6_2: LD6.2 T1.3(C)
NetLD8_1: LD8.1 R90.1
NetR65_2: R65.2 X3.1(EN)
NetR75_1: R75.1 R76.2 SB40.1 U20.27(RESETB)
NetR81_1: R81.1 U20.24(RBIAS)
NetR83_2: R83.2 R86.1 T1.1(B)
NetR85_1: R85.1 U20.22(VBUS)
NetR95_1: R95.1 U20.17(CPEN) U25.4(EN)
NetSB41_1: SB41.1 SB42.1 U20.26(REFCLK)
NetSB42_2: SB42.2 X3.3(OUT)

Not connected (* = marked no-connect by the designer): U20 12(NC)* 15(SPK_L)* 16(SPK_R)* 25(XO)*; U23 4(NC)*

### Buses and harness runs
bus ULPI_D[0..7] = port ULPI_D[0..7]

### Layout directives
differential pair: USB_HS_CN18_N, USB_HS_CN18_P, USB_HS_N, USB_HS_P

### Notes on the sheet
- USB_OTG_HS
- PH4
- PI11
- PC0
- PA5
- PB10
- PB11
- PB12
- PB13
- PB5
- PA3
- PB0
- PB1
- (near SB42) 24MHz

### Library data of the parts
C102 C108 C111 C117 C118 = MCD-00006: as C90 on sheet Peripherals
C120 = MCD-00012: Capacitor, MLCC, 2.2uF, 10V, X5R, 10%, 0603, T=0,8mm; Manufacturer_Part_Number: CC0603KRX5R6BB225; Manufacturer: YAGEO; Alternate_Manufacturer_Part_Number: C0603C225K8PACTU; Alternate_Manufacturer: KEMET; BMS_Part_Number: 9142010; Part_Preference: Recommended; Partial_Alternate_Internal_Part_Number: MCD-00551; Provided_By: SUBCO; Component_Country_Of_Origin: China; ID: 2467; Order_Code_RS: 2370679; ShowFields: YES
C124 = MCD-00007: Capacitor, Tantalum, 4.7uF, 16V, 10%, TypeA; Manufacturer_Part_Number: TAJA475K016R; Manufacturer: AVX; Part_Preference: Recommended; Partial_Alternate_Internal_Part_Number: MCD-03149; Provided_By: SUBCO; Component_Country_Of_Origin: El Salvador; ID: 2473; Order_Code_RS: 197269; ShowFields: YES
CN15 = MCD-00661: USB-MICRO-AB Receptacle, RA, SMT + DIP, Standard, Top Mount, USB certified (symbol & footprint compatible with MCD-00022); Part_Type: Connector; Manufacturer_Part_Number: ZX62RD-AB-5P8(30); Manufacturer: HIROSE; Part_Preference: Recommended; Provided_By: SUBCO; Component_Country_Of_Origin: Japan; ID: 3083; Order_Code_RS: 136-1404; ShowFields: YES
LD6 = MCD-00588: LED Green, 0603 SMD, Forward Voltage Typ=2V, Max=2.5V; Part_Type: Display; Manufacturer_Part_Number: LG Q396-PS-35; Manufacturer: OSRAM OPTO SEMICONDUCTORS; Alternate_Manufacturer_Part_Number: VLMTG1300-GS08; Alternate_Manufacturer: VISHAY SEMICONDUCTOR OPTO DIVISION; Part_Preference: Recommended; Partial_Alternate_Internal_Part_Number: MCD-02400, MCD-03155; Provided_By: SUBCO; Component_Country_Of_Origin: Unknown; ID: 3155; ShowFields: YES
LD8 = MCD-00587: as LD3 on sheet Peripherals
R65 R86 R95 = MCD-00053: Resistor,10K,0402,1%,1/16W; Manufacturer_Part_Number: RC0402FR-0710KL; Manufacturer: YAGEO; BMS_Part_Number: 9131590; Part_Preference: Recommended; Provided_By: SUBCO; Component_Country_Of_Origin: China; ID: 2539; Order_Code_RS: 9239359; ShowFields: YES
R72 R88 R89 R100 R101 R103 R104 = MCD-00056: Resistor,0R,0603,5%,1/10W; Manufacturer_Part_Number: RC0603JR-070RL; Manufacturer: YAGEO; Part_Preference: Recommended; Provided_By: SUBCO; Component_Country_Of_Origin: China; ID: 2536; Order_Code_RS: 9233130RL; ShowFields: YES
R75 = MCD-00065: Resistor,4K7,0402,1%,1/16W; Manufacturer_Part_Number: RC0402FR-074K7L; Manufacturer: YAGEO; Alternate_Manufacturer_Part_Number: RT0402FRE074K7L; Part_Preference: Recommended; Partial_Alternate_Internal_Part_Number: MCD-03300; Provided_By: SUBCO; Component_Country_Of_Origin: China; ID: 2526; Order_Code_RS: 9239316; ShowFields: YES
R76 = MCD-00059: as R11 on sheet Peripherals
R80 = MCD-00197: Resistor,330R,0603,1%,1/10W; Manufacturer_Part_Number: RC0603FR-07330RL; Manufacturer: YAGEO; BMS_Part_Number: 9129729; Part_Preference: Recommended; Provided_By: SUBCO; Component_Country_Of_Origin: China; ID: 2672; ShowFields: YES
R81 = MCD-00570: Resistor,8K06,0603,1%,1/10W; Manufacturer_Part_Number: RC0603FR-078K06L; Manufacturer: YAGEO; Part_Preference: Recommended; Provided_By: SUBCO; Component_Country_Of_Origin: China; ID: 3177; ShowFields: YES
R83 = MCD-00063: as R5 on sheet SDcard
R84 = MCD-00179: Resistor,0R,0805,5%; Manufacturer_Part_Number: RC0805JR-070RL; Manufacturer: YAGEO; Part_Preference: Recommended; Provided_By: SUBCO; Component_Country_Of_Origin: China; ID: 2685; ShowFields: YES
R85 = MCD-00528: Resistor,820R,0603,1%,1/10W; Manufacturer_Part_Number: RC0603FR-07820RL; Manufacturer: YAGEO; BMS_Part_Number: 9129759; Part_Preference: Recommended; Provided_By: SUBCO; Component_Country_Of_Origin: China; ID: 3218; ShowFields: YES
R90 = MCD-00500: Resistor,620R,0603,1%,1/10W; Manufacturer_Part_Number: RC0603FR-07620RL; Manufacturer: YAGEO; Part_Preference: Recommended; Provided_By: SUBCO; Component_Country_Of_Origin: China; ID: 2778; ShowFields: YES
R102 = MCD-00184: Resistor,3K3,0402,1%,1/16W; Manufacturer_Part_Number: RC0402FR-073K3L; Manufacturer: YAGEO; BMS_Part_Number: 9131946; Part_Preference: Recommended; Provided_By: SUBCO; Component_Country_Of_Origin: China; ID: 2684; ShowFields: YES
SB40-SB42 = MCD-00071: as SB6-SB19 on sheet Peripherals
T1 = MCD-00073: NPN Bipolar Transistor; Manufacturer_Part_Number: BSR14; Manufacturer: ON SEMICONDUCTOR; Part_Type: IC; Alternate_Manufacturer_Part_Number: MMBT2222ALT1G / MMBT2222ALT3G; Part_Preference: Recommended; Partial_Alternate_Internal_Part_Number: MCD-01737, MCD-03305, , MCD-02988; Provided_By: SUBCO; Component_Country_Of_Origin: Unknown; ID: 2519; ShowFields: YES
U20 = MCD-00569: USB3320C,  Hi-Speed USB Host, Device or OTG PHY with ULPI Low Pin Interface; Manufacturer: MICROCHIP; Part_Type: IC; Part_Preference: Recommended; Provided_By: SUBCO; Component_Country_Of_Origin: Unknown; ID: 3179; Order_Code_RS: 889-5840; ShowFields: YES
U21 = MCD-00251: High power transient voltage suppressor, 7V breakdown; Part_Type: Diode; Manufacturer: STMICROELECTRONICS; BMS_Part_Number: 9179042; Manufacturer_HQ_COO: EU; Part_Preference: Recommended; Provided_By: SUBCO with ST control; Component_Country_Of_Origin: China; ID: 2618; Order_Code_RS: 110-6381; ShowFields: YES
U23 = MCD-00649: Common mode filter with ESD protection for USB 2.0 interface; Part_Type: Diode; Manufacturer: STMICROELECTRONICS; BMS_Part_Number: 9151138; Manufacturer_HQ_COO: EU; Part_Preference: Recommended; Provided_By: SUBCO with ST control; Component_Country_Of_Origin: China; ID: 3094; Order_Code_RS: 880-5276; ShowFields: YES
U25 = MCD-00159: 500mA, Enhanced single channel power switches with active high enable pin; Manufacturer: STMICROELECTRONICS; Part_Type: IC; Alternate_Manufacturer_Part_Number: TPS2051C; Alternate_Manufacturer: TEXAS INSTRUMENTS; BMS_Part_Number: 9159009; Manufacturer_HQ_COO: EU; Part_Preference: Recommended; Provided_By: SUBCO with ST control; Component_Country_Of_Origin: Malaysia; ID: 2708; Order_Code_RS: 165-5516; ShowFields: YES
U26 = MCD-00170: as U2 on sheet Peripherals
X3 = MCD-01976: Oscillator 24Mhz, +-50ppm, Vcc:3.3V typ, square wave: [0.1Vcc;0.9Vcc], Enable pin, SMD; Part_Type: Crystal_Osc; Part_Preference: Recommended; Manufacturer: NDK; Manufacturer_Part_Number: NZ2520SH-24MHZ-END4869D; Component_Country_Of_Origin: Unknown; ID: 4076; ShowFields: YES

## Sheet MCU.SchDoc: MCU STM32H7B3LIH6Q
size A3; Date: Not used; ApprovedBy: Not used; CheckedBy: Not used; Author: Not used; CompanyName: STMicroelectronics; DrawnBy: Not used; Engineer: Not used; Organization: Not used; Address1: Not used; Address2: Not used; Address3: Not used; Address4: Not used; DocumentNumber: Not used; Revision: Not used; SheetNumber: 3; SheetTotal: 17
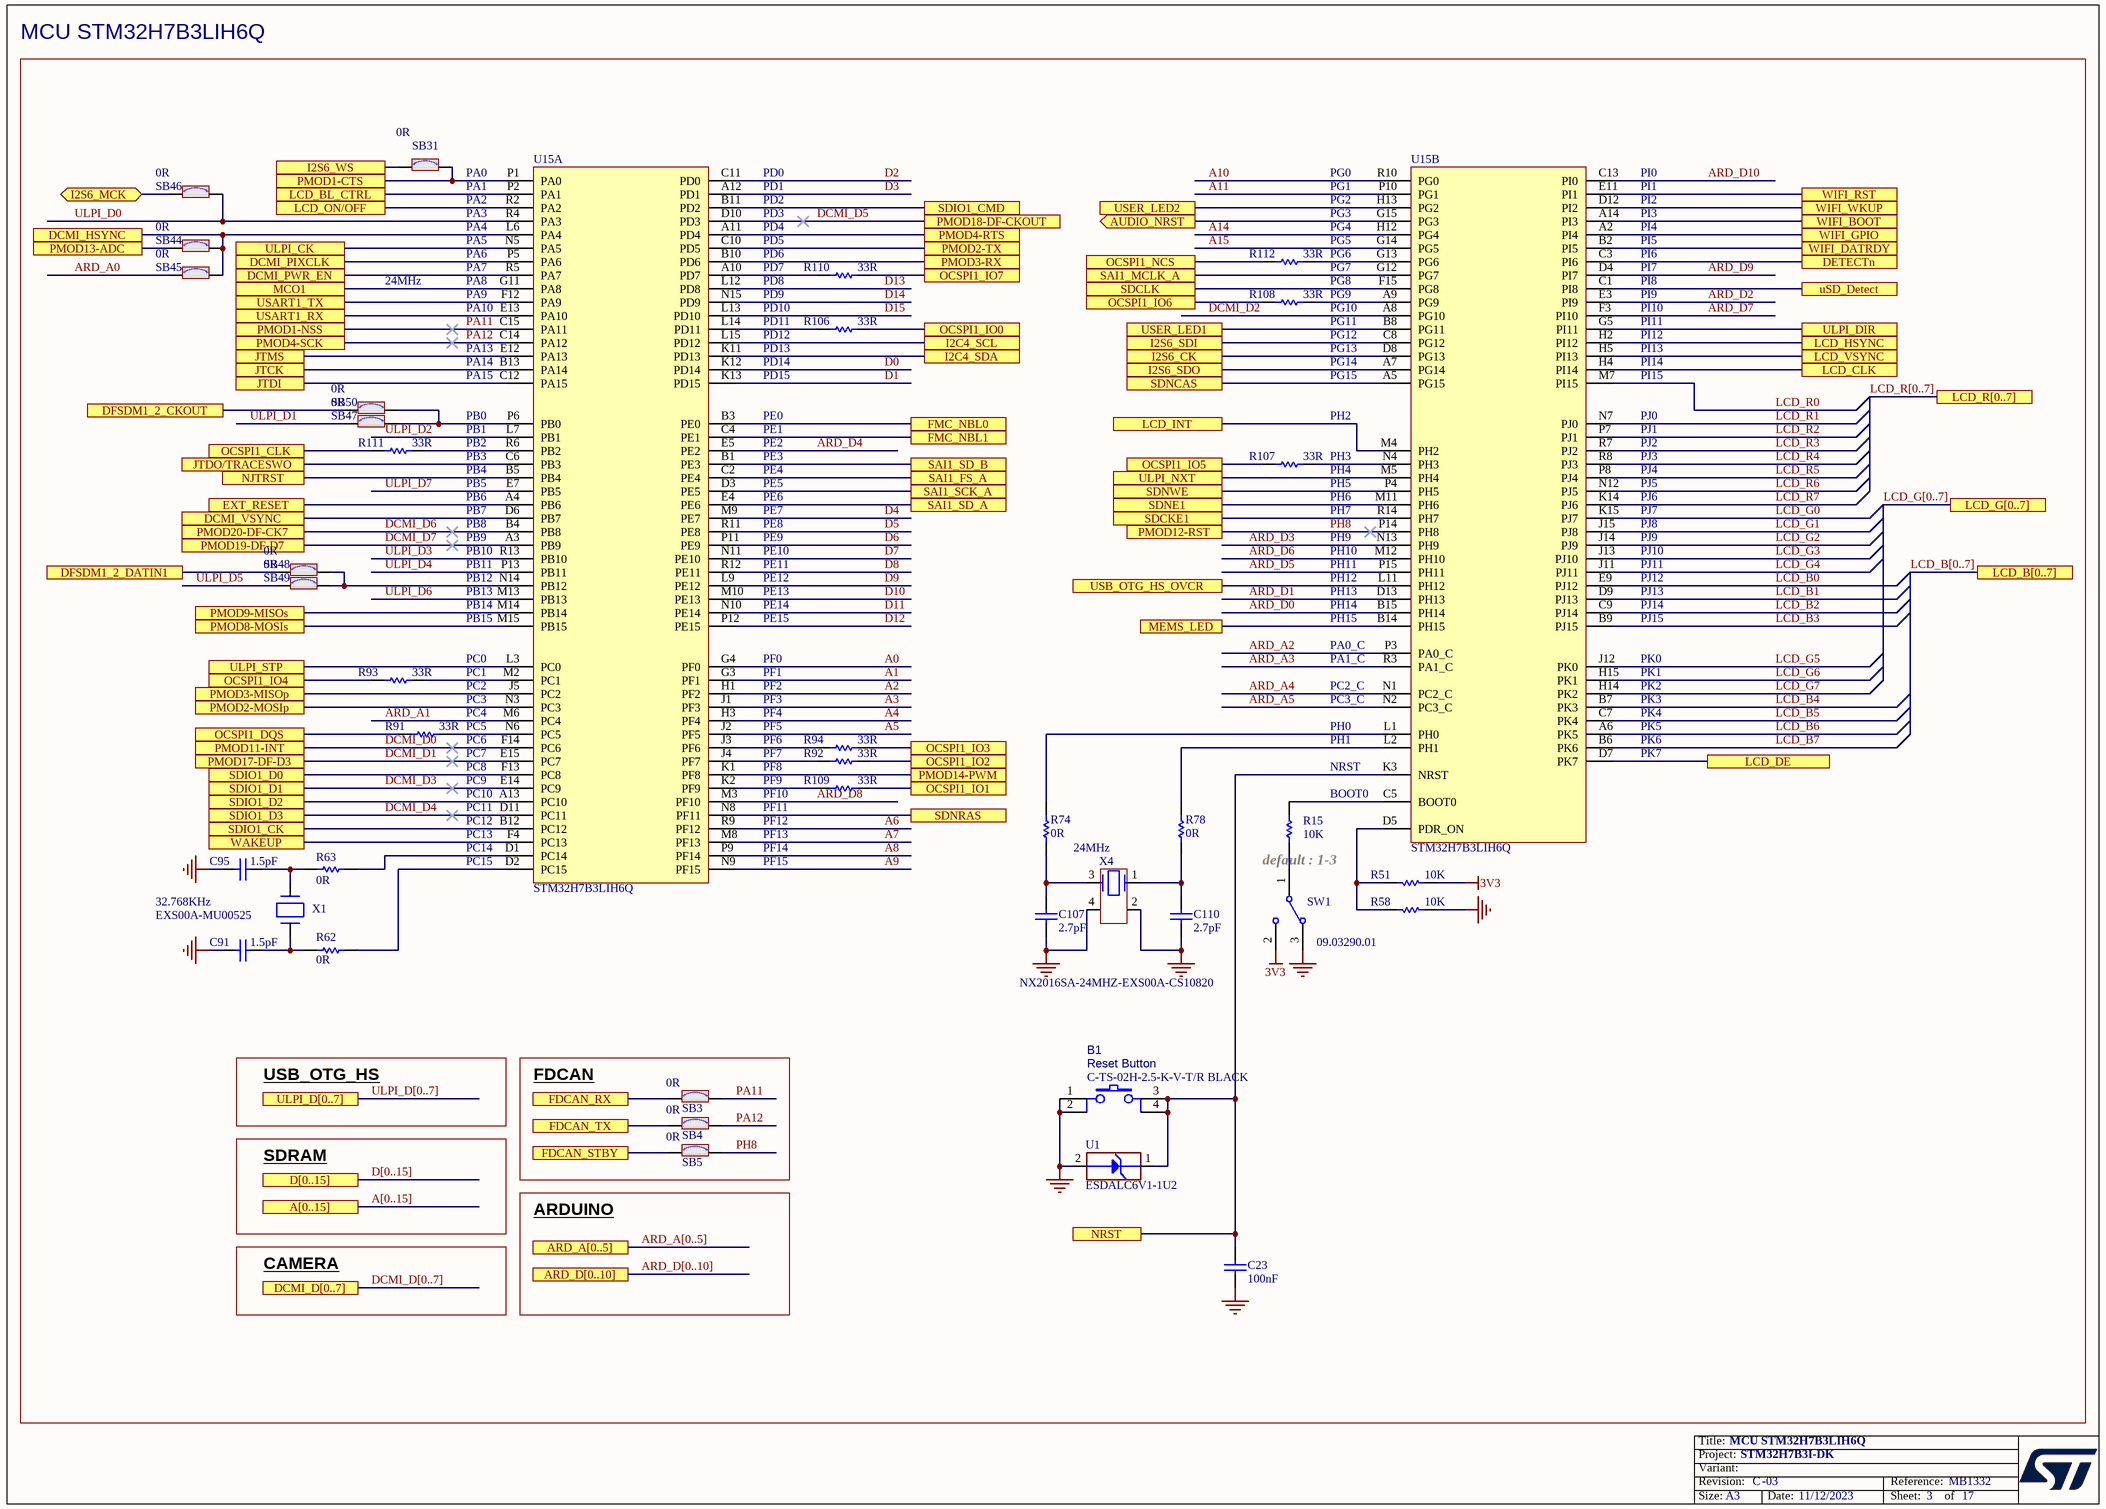
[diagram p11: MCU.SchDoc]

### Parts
B1  value C-TS-02H-2.5-K-V-T/R BLACK  [SWI_JIUBABA_C-TS-02H-2-5-K-V-T_R_BLACK]  (hidden comment: SW-PUSH-TS-02H-Black)
C23  value 100nF  [C0402]  (hidden comment: Capacitor)
C91  value 1.5pF  [C0402]  (hidden comment: Capacitor)
C95  value 1.5pF  [C0402]  (hidden comment: Capacitor)
C107  value 2.7pF  [C0402]  (hidden comment: Capacitor)
C110  value 2.7pF  [C0402]  (hidden comment: Capacitor)
R15  value 10K  [R0402]  (hidden comment: Resistor)
R51  value 10K  [R0402]  (hidden comment: Resistor)
R58  value 10K  [R0402]  (hidden comment: Resistor)
R62  value 0R  [R0402]  (hidden comment: Resistor)
R63  value 0R  [R0402]  (hidden comment: Resistor)
R74  value 0R  [R0402]  (hidden comment: Resistor)
R78  value 0R  [R0402]  (hidden comment: Resistor)
R91  value 33R  [R0402]  (hidden comment: Resistor)
R92  value 33R  [R0402]  (hidden comment: Resistor)
R93  value 33R  [R0402]  (hidden comment: Resistor)
R94  value 33R  [R0402]  (hidden comment: Resistor)
R106  value 33R  [R0402]  (hidden comment: Resistor)
R107  value 33R  [R0402]  (hidden comment: Resistor)
R108  value 33R  [R0402]  (hidden comment: Resistor)
R109  value 33R  [R0402]  (hidden comment: Resistor)
R110  value 33R  [R0402]  (hidden comment: Resistor)
R111  value 33R  [R0402]  (hidden comment: Resistor)
R112  value 33R  [R0402]  (hidden comment: Resistor)
SB3  value 0R  [SOLDER-BRIDGE_R0603-0R]  (hidden comment: SB_ON)
SB4  value 0R  [SOLDER-BRIDGE_R0603-0R]  (hidden comment: SB_ON)
SB5  value 0R  [SOLDER-BRIDGE_R0603-0R]  (hidden comment: SB_ON)
SB31  value 0R  [SOLDER-BRIDGE_R0603-0R]  (hidden comment: SB_ON)
SB44  value 0R  [SOLDER-BRIDGE_R0603-0R]  (hidden comment: SB_ON)
SB45  value 0R  [SOLDER-BRIDGE_R0603-0R]  (hidden comment: SB_ON)
SB46  value 0R  [SOLDER-BRIDGE_R0603-0R]  (hidden comment: SB_ON)
SB47  value 0R  [SOLDER-BRIDGE_R0603-0R]  (hidden comment: SB_ON)
SB48  value 0R  [SOLDER-BRIDGE_R0603-0R]  (hidden comment: SB_ON)
SB49  value 0R  [SOLDER-BRIDGE_R0603-0R]  (hidden comment: SB_ON)
SB50  value 0R  [SOLDER-BRIDGE_R0603-0R]  (hidden comment: SB_ON)
SW1  value 09.03290.01  [SWI_EAO_09-03290-01_EXTENDED_STRAIGHT_BLACK]  (hidden comment: SW_MECA_1K2)
U1  value ESDALC6V1-1U2  [ESD_ST0201]  (hidden comment: ESD-TRANSIL)
U15  value STM32H7B3LIH6Q  [ICC_TFBGA225_13X13_STM32H7B3NIH6Q_P080]  (hidden comment: STM32H7B3NIH6Q)  (parts A,B of 3)
X1  value 32.768KHz  [CRY_NX3215SA_2P]  (hidden comment: XTAL_2_PINS)
X4  value 24MHz  Manufacturer_Part_Number: NX2016SA-24MHZ-EXS00A-CS10820  [CRY_NX2016SA_4P]  (hidden comment: XTAL_4_PINS)

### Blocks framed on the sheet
FDCAN: SB3-SB5

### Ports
A[0..15], ARD_A[0..5], ARD_D[0..10], AUDIO_NRST (out), D[0..15], DCMI_D[0..7], DCMI_HSYNC, DCMI_PIXCLK, DCMI_PWR_EN, DCMI_VSYNC, DETECTn, DFSDM1_2_CKOUT, DFSDM1_2_DATIN1, EXT_RESET, FDCAN_RX, FDCAN_STBY, FDCAN_TX, FMC_NBL0, FMC_NBL1, I2C4_SCL, I2C4_SDA, I2S6_CK, I2S6_MCK (bidir), I2S6_SDI, I2S6_SDO, I2S6_WS, JTCK, JTDI, JTDO/TRACESWO, JTMS, LCD_B[0..7], LCD_BL_CTRL, LCD_CLK, LCD_DE, LCD_G[0..7], LCD_HSYNC, LCD_INT, LCD_ON/OFF, LCD_R[0..7], LCD_VSYNC, MCO1, MEMS_LED, NJTRST, NRST, OCSPI1_CLK, OCSPI1_DQS, OCSPI1_IO0, OCSPI1_IO1, OCSPI1_IO2, OCSPI1_IO3, OCSPI1_IO4, OCSPI1_IO5, OCSPI1_IO6, OCSPI1_IO7, OCSPI1_NCS, PMOD1-CTS, PMOD1-NSS, PMOD2-MOSIp, PMOD2-TX, PMOD3-MISOp, PMOD3-RX, PMOD4-RTS, PMOD4-SCK, PMOD8-MOSIs, PMOD9-MISOs, PMOD11-INT, PMOD12-RST, PMOD13-ADC, PMOD14-PWM, PMOD17-DF-D3, PMOD18-DF-CKOUT, PMOD19-DF-D7, PMOD20-DF-CK7, SAI1_FS_A, SAI1_MCLK_A, SAI1_SCK_A, SAI1_SD_A, SAI1_SD_B, SDCKE1, SDCLK, SDIO1_CK, SDIO1_CMD, SDIO1_D0, SDIO1_D1, SDIO1_D2, SDIO1_D3, SDNCAS, SDNE1, SDNRAS, SDNWE, ULPI_CK, ULPI_D[0..7], ULPI_DIR, ULPI_NXT, ULPI_STP, USART1_RX, USART1_TX, USB_OTG_HS_OVCR, uSD_Detect, USER_LED1, USER_LED2, WAKEUP, WIFI_BOOT, WIFI_DATRDY, WIFI_GPIO, WIFI_RST, WIFI_WKUP

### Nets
3V3: R51.1 SW1.2
GND: B1.1 B1.2 C23.1 C91.1 C95.1 C107.1 C110.1 R58.1 SW1.3 U1.2(GND) X4.2 X4.4
2_CTS: SB31.1 U15.P1(PA0) ; port PMOD1-CTS
2_RTS: U15.A11(PD4) ; port PMOD4-RTS
2_RX: U15.B10(PD6) ; port PMOD3-RX
2_TX: U15.C10(PD5) ; port PMOD2-TX
A0: U15.G4(PF0)
A1: U15.G3(PF1)
A2: U15.H1(PF2)
A3: U15.J1(PF3)
A4: U15.H3(PF4)
A5: U15.J2(PF5)
A6: U15.R9(PF12)
A7: U15.M8(PF13)
A8: U15.P9(PF14)
A9: U15.N9(PF15)
A10: U15.R10(PG0)
A11: U15.P10(PG1)
A14: U15.H12(PG4)
A15: U15.G14(PG5)
ARD_A0: SB45.2
ARD_A1: U15.M6(PC4)
ARD_A2: U15.P3(PA0_C)
ARD_A3: U15.R3(PA1_C)
ARD_A4: U15.N1(PC2_C)
ARD_A5: U15.N2(PC3_C)
ARD_D0: U15.B15(PH14)
ARD_D1: U15.D13(PH13)
ARD_D2: U15.E3(PI9)
ARD_D3: U15.N13(PH9)
ARD_D4: U15.E5(PE2)
ARD_D5: U15.P15(PH11)
ARD_D6: U15.M12(PH10)
ARD_D7: U15.F3(PI10)
ARD_D8: U15.M3(PF10)
ARD_D9: U15.D4(PI7)
ARD_D10: U15.C13(PI0)
AUDIO_NRST: U15.G15(PG3) ; port AUDIO_NRST
CKOUT: SB50.2 ; port DFSDM1_2_CKOUT
D0: U15.K12(PD14)
D1: U15.K13(PD15)
D2: U15.C11(PD0)
D3: U15.A12(PD1)
D4: U15.M9(PE7)
D5: U15.R11(PE8)
D6: U15.P11(PE9)
D7: U15.N11(PE10)
D8: U15.R12(PE11)
D9: U15.L9(PE12)
D10: U15.M10(PE13)
D11: U15.N10(PE14)
D12: U15.P12(PE15)
D13: U15.L12(PD8)
D14: U15.N15(PD9)
D15: U15.L13(PD10)
DCMI_D0: U15.F14(PC6) ; port PMOD11-INT
DCMI_D1: U15.E15(PC7) ; port PMOD17-DF-D3
DCMI_D2: U15.A8(PG10)
DCMI_D3: U15.E14(PC9) ; port SDIO1_D1
DCMI_D4: U15.D11(PC11) ; port SDIO1_D3
DCMI_D5: U15.D10(PD3) ; port PMOD18-DF-CKOUT
DCMI_D6: U15.B4(PB8) ; port PMOD20-DF-CK7
DCMI_D7: U15.A3(PB9) ; port PMOD19-DF-D7
DCMI_HSYNC: SB44.1 SB45.1 U15.L6(PA4) ; port DCMI_HSYNC
DCMI_PIXCLK: U15.P5(PA6) ; port DCMI_PIXCLK
DCMI_PWR_EN: U15.R5(PA7) ; port DCMI_PWR_EN
DCMI_VSYNC: U15.D6(PB7) ; port DCMI_VSYNC
DETECTn: U15.C3(PI6) ; port DETECTn
DFSDM1_2_DATIN1: SB48.2 ; port DFSDM1_2_DATIN1
EXT_RESET: U15.A4(PB6) ; port EXT_RESET
FDCAN_RX: SB3.1 ; port FDCAN_RX
FDCAN_STBY: SB5.1 ; port FDCAN_STBY
FDCAN_TX: SB4.1 ; port FDCAN_TX
FMC_NBL0: U15.B3(PE0) ; port FMC_NBL0
FMC_NBL1: U15.C4(PE1) ; port FMC_NBL1
I2C4_SCL: U15.L15(PD12) ; port I2C4_SCL
I2C4_SDA: U15.K11(PD13) ; port I2C4_SDA
I2S6_CK: U15.D8(PG13) ; port I2S6_CK
I2S6_MCK: SB46.2 ; port I2S6_MCK
I2S6_SDI: U15.C8(PG12) ; port I2S6_SDI
I2S6_SDO: U15.A7(PG14) ; port I2S6_SDO
I2S6_WS: SB31.2 ; port I2S6_WS
JTDI: U15.C12(PA15) ; port JTDI
LCD_B0: U15.E9(PJ12)
LCD_B1: U15.D9(PJ13)
LCD_B2: U15.C9(PJ14)
LCD_B3: U15.B9(PJ15)
LCD_B4: U15.B7(PK3)
LCD_B5: U15.C7(PK4)
LCD_B6: U15.A6(PK5)
LCD_B7: U15.B6(PK6)
LCD_BL_CTRL: U15.P2(PA1) ; port LCD_BL_CTRL
LCD_CLK: U15.H4(PI14) ; port LCD_CLK
LCD_DE: U15.D7(PK7) ; port LCD_DE
LCD_G0: U15.K15(PJ7)
LCD_G1: U15.J15(PJ8)
LCD_G2: U15.J14(PJ9)
LCD_G3: U15.J13(PJ10)
LCD_G4: U15.J11(PJ11)
LCD_G5: U15.J12(PK0)
LCD_G6: U15.H15(PK1)
LCD_G7: U15.H14(PK2)
LCD_HSYNC: U15.H2(PI12) ; port LCD_HSYNC
LCD_INT: U15.M4(PH2) ; port LCD_INT
LCD_ON/OFF: U15.R2(PA2) ; port LCD_ON/OFF
LCD_R0: U15.M7(PI15)
LCD_R1: U15.N7(PJ0)
LCD_R2: U15.P7(PJ1)
LCD_R3: U15.R7(PJ2)
LCD_R4: U15.R8(PJ3)
LCD_R5: U15.P8(PJ4)
LCD_R6: U15.N12(PJ5)
LCD_R7: U15.K14(PJ6)
LCD_VSYNC: U15.H5(PI13) ; port LCD_VSYNC
MCO1: U15.G11(PA8) ; port MCO1
MEMS_LED: U15.B14(PH15) ; port MEMS_LED
MISO: U15.J5(PC2) ; port PMOD3-MISOp
MOSI: U15.N3(PC3) ; port PMOD2-MOSIp
NJTRST: U15.B5(PB4) ; port NJTRST
OCSPI1_CLK: R111.1 ; port OCSPI1_CLK
OCSPI1_DQS: R91.1 ; port OCSPI1_DQS
OCSPI1_IO0: R106.2 ; port OCSPI1_IO0
OCSPI1_IO1: R109.2 ; port OCSPI1_IO1
OCSPI1_IO2: R92.2 ; port OCSPI1_IO2
OCSPI1_IO3: R94.2 ; port OCSPI1_IO3
OCSPI1_IO4: R93.1 ; port OCSPI1_IO4
OCSPI1_IO5: R107.1 ; port OCSPI1_IO5
OCSPI1_IO6: R108.1 ; port OCSPI1_IO6
OCSPI1_IO7: R110.2 ; port OCSPI1_IO7
OCSPI1_NCS: R112.1 ; port OCSPI1_NCS
PA11: SB3.2 U15.C15(PA11) ; port PMOD1-NSS  [project net nSS]
PA12: SB4.2 U15.C14(PA12) ; port PMOD4-SCK
PH8: SB5.2 U15.P14(PH8) ; port PMOD12-RST
PMOD8-MOSIs: U15.M15(PB15) ; port PMOD8-MOSIs
PMOD9: U15.M14(PB14) ; port PMOD9-MISOs
PMOD13-ADC: SB44.2 ; port PMOD13-ADC
PMOD14-PWM: U15.K1(PF8) ; port PMOD14-PWM
SAI1_FS_A: U15.C2(PE4) ; port SAI1_FS_A
SAI1_MCLK_A: U15.G12(PG7) ; port SAI1_MCLK_A
SAI1_SCK_A: U15.D3(PE5) ; port SAI1_SCK_A
SAI1_SD_A: U15.E4(PE6) ; port SAI1_SD_A
SAI1_SD_B: U15.B1(PE3) ; port SAI1_SD_B
SDCKE1: U15.R14(PH7) ; port SDCKE1
SDCLK: U15.F15(PG8) ; port SDCLK
SDIO1_CK: U15.B12(PC12) ; port SDIO1_CK
SDIO1_CMD: U15.B11(PD2) ; port SDIO1_CMD
SDIO1_D0: U15.F13(PC8) ; port SDIO1_D0
SDIO1_D2: U15.A13(PC10) ; port SDIO1_D2
SDNCAS: U15.A5(PG15) ; port SDNCAS
SDNE1: U15.M11(PH6) ; port SDNE1
SDNRAS: U15.N8(PF11) ; port SDNRAS
SDNWE: U15.P4(PH5) ; port SDNWE
T_NRST: B1.3 B1.4 C23.2 U1.1(IO1) U15.K3(NRST) ; port NRST
T_SWCLK: U15.B13(PA14) ; port JTCK
T_SWDIO: U15.E12(PA13) ; port JTMS
T_SWO: U15.C6(PB3) ; port JTDO/TRACESWO
ULPI_CK: U15.N5(PA5) ; port ULPI_CK
ULPI_D0: SB46.1 U15.R4(PA3)
ULPI_D1: SB47.2
ULPI_D2: U15.L7(PB1)
ULPI_D3: U15.R13(PB10)
ULPI_D4: U15.P13(PB11)
ULPI_D5: SB49.2
ULPI_D6: U15.M13(PB13)
ULPI_D7: U15.E7(PB5)
ULPI_DIR: U15.G5(PI11) ; port ULPI_DIR
ULPI_NXT: U15.M5(PH4) ; port ULPI_NXT
ULPI_STP: U15.L3(PC0) ; port ULPI_STP
USART1_RX: U15.E13(PA10) ; port USART1_RX
USART1_TX: U15.F12(PA9) ; port USART1_TX
USB_OTG_HS_OVCR: U15.L11(PH12) ; port USB_OTG_HS_OVCR
uSD_Detect: U15.C1(PI8) ; port uSD_Detect
USER_LED1: U15.B8(PG11) ; port USER_LED1
USER_LED2: U15.H13(PG2) ; port USER_LED2
WAKEUP: U15.F4(PC13) ; port WAKEUP
WIFI_BOOT: U15.A14(PI3) ; port WIFI_BOOT
WIFI_DATRDY: U15.B2(PI5) ; port WIFI_DATRDY
WIFI_GPIO: U15.A2(PI4) ; port WIFI_GPIO
WIFI_RST: U15.E11(PI1) ; port WIFI_RST
WIFI_WKUP: U15.D12(PI2) ; port WIFI_WKUP
NetC91_2: C91.2 R62.1 X1.2(X2)
NetC95_2: C95.2 R63.1 X1.1(X1)
NetC107_2: C107.2 R74.1 X4.3
NetC110_2: C110.2 R78.1 X4.1
NetR15_1: R15.1 U15.C5(BOOT0)
NetR15_2: R15.2 SW1.1
NetR51_2: R51.2 R58.2 U15.D5(PDR_ON)
NetR62_2: R62.2 U15.D2(PC15)
NetR63_2: R63.2 U15.D1(PC14)
NetR74_2: R74.2 U15.L1(PH0)
NetR78_2: R78.2 U15.L2(PH1)
NetR91_2: R91.2 U15.N6(PC5)
NetR92_1: R92.1 U15.J4(PF7)
NetR93_2: R93.2 U15.M2(PC1)
NetR94_1: R94.1 U15.J3(PF6)
NetR106_1: R106.1 U15.L14(PD11)
NetR107_2: R107.2 U15.N4(PH3)
NetR108_2: R108.2 U15.A9(PG9)
NetR109_1: R109.1 U15.K2(PF9)
NetR110_1: R110.1 U15.A10(PD7)
NetR111_2: R111.2 U15.R6(PB2)
NetR112_2: R112.2 U15.G13(PG6)
NetSB47_1: SB47.1 SB50.1 U15.P6(PB0)
NetSB48_1: SB48.1 SB49.1 U15.N14(PB12)

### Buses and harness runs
bus A[0..15] = port A[0..15]
bus ARD_A[0..5] = port ARD_A[0..5]
bus ARD_D[0..10] = port ARD_D[0..10]
bus D[0..15] = port D[0..15]
bus DCMI_D[0..7] = port DCMI_D[0..7]
bus LCD_B[0..7] = port LCD_B[0..7]
bus LCD_G[0..7] = port LCD_G[0..7]
bus LCD_R[0..7] = port LCD_R[0..7]
bus ULPI_D[0..7] = port ULPI_D[0..7]

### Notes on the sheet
- MCU STM32H7B3LIH6Q
- (near SB31) PA0
- PD0
- PG0
- PI0
- PA1
- PA2
- PA3
- PA4
- PA5
- PD1
- PD2
- PD3
- PD4
- PD5
- PG1
- PG2
- PG3
- (near R112) PG4
- (near R112) PG5
- PI1
- PI2
- PI3
- PI4
- PI5
- 24MHz
- (near U15) PA6
- (near U15) PA7
- (near U15) PA8
- (near U15) PA9
- (near U15) PA10
- PD6
- PD7
- PD8
- PD9
- PD10
- (near R112) PG6
- PG7
- PG8
- PG9
- (near R108) PG10
- PI6
- PI7
- PI8
- PI9
- PI10
- (near U15) PA13
- (near U15) PA14
- (near U15) PA15
- PD11
- PD12
- PD13
- PD14
- PD15
- (near R108) PG11
- PG12
- PG13
- PG14
- PG15
- PI11
- PI12
- PI13
- PI14
- PI15
- PB0
- PB1
- PB2
- PE0
- PE1
- PE2
- PH2
- PJ0
- PJ1
- PJ2
- PB3
- PB4
- PB5
- PB6
- PB7
- PE3
- PE4
- PE5
- PE6
- PE7
- (near R107) PH3
- (near R107) PH4
- (near R107) PH5
- (near R107) PH6
- PH7
- PJ3
- PJ4
- PJ5
- PJ6
- PJ7
- (near U15) PB8
- (near U15) PB9
- (near U15) PB10
- (near U15) PB11
- (near U15) PB12
- PE8
- PE9
- PE10
- PE11
- PE12
- PH9
- PH10
- PH11
- PH12
- PJ8
- PJ9
- PJ10
- PJ11
- PJ12
- (near U15) PB13
- (near U15) PB14
- (near U15) PB15
- PE13
- PE14
- PE15
- PH13
- PH14
- PH15
- (near U15) PA0_C
- PJ13
- PJ14
- PJ15
- PC0
- PC1
- PC2
- PC3
- PC4
- PF0
- PF1
- PF2
- PF3
- PF4
- (near U15) PA1_C
- (near U15) PC2_C
- (near U15) PC3_C
- PK0
- PK1
- PK2
- PK3
- PK4
- (near R91) PC5
- (near R91) PC6
- PC7
- PC8
- PC9
- PF5
- PF6
- PF7
- PF8
- PF9
- PH0
- PH1
- NRST
- PK5
- PK6
- PK7
- PC10
- (near U15) PC11
- (near U15) PC12
- (near U15) PC13
- (near U15) PC14
- PF10
- PF11
- PF12
- PF13
- PF14
- BOOT0
- EXS00A-MU00525
- (near U15) PC15
- PF15
- (near R15) default : 1-3
- USB_OTG_HS
- (near B1) Reset Button
- SDRAM
- ARDUINO
- CAMERA

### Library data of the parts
B1 = MCD-00171: Switch HW SMD black; Part_Type: Misc; Manufacturer: JIUBABA; Part_Preference: Alternate; Provided_By: SUBCO; Alternate_EMS: A; Component_Country_Of_Origin: Unknown; ID: 2699; ShowFields: YES
C23 = MCD-00006: as C90 on sheet Peripherals
C91 C95 = MCD-00563: Capacitor, MLCC, 1.5pF, 50V, NPO, +-0.25pF, 0402, T=0,5mm; Manufacturer_Part_Number: CC0402CRNPO9BN1R5; Manufacturer: YAGEO; Part_Preference: Recommended; Partial_Alternate_Internal_Part_Number: MCD-01460; Provided_By: SUBCO; Component_Country_Of_Origin: China; ID: 3175; ShowFields: YES
C107 C110 = MCD-01727: Capacitor, MLCC, 2.7pF, 50V, NPO, -+0.25pF 0402; Manufacturer_Part_Number: CC0402CRNPO9BN2R7; Manufacturer: YAGEO; Part_Preference: Recommended; Provided_By: SUBCO; Component_Country_Of_Origin: China; ID: 3827; ShowFields: YES
R15 R51 R58 = MCD-00053: as R65 on sheet USB_OTG_HS_externalPHY
R62 R63 R74 R78 = MCD-00052: Resistor,0R,0402,5%,1/16W; Manufacturer_Part_Number: RC0402JR-070RL; Manufacturer: YAGEO; Part_Preference: Recommended; Provided_By: SUBCO; Component_Country_Of_Origin: China; ID: 2540; Order_Code_RS: 9232516RL; ShowFields: YES
R91-R94 R106-R112 = MCD-00455: Resistor,33R,0402,1%,1/16W; Manufacturer_Part_Number: RC0402FR-0733RL; Manufacturer: YAGEO; Part_Preference: Recommended; Provided_By: SUBCO; Component_Country_Of_Origin: China; ID: 2821; ShowFields: YES
SB3-SB5 SB31 SB44-SB50 = MCD-00071: as SB6-SB19 on sheet Peripherals
SW1 = MCD-00566: Mechanical Slide Switches 1K2 BLK ACT GOLD STRT MNT; Part_Type: Misc; Manufacturer: EAO; Part_Preference: Recommended; Provided_By: SUBCO; Component_Country_Of_Origin: Switzerland; ID: 3181; Order_Code_RS: 204-7865; ShowFields: YES
U1 = MCD-00170: as U2 on sheet Peripherals
U15 = MCD-01929: MCU, ARM Cortex-M7 32-bit, 2MB Flash, 1.4MB RAM, With Crypto, SMPS; Part_Type: IC; Manufacturer: STMICROELECTRONICS; BMS_Part_Number: 9175358; Part_Preference: Recommended; Manufacturer_HQ_COO: EU; Order_Code_RS: 201-4447; Component_Country_Of_Origin: Philippines; ShowFields: YES; ID: 4029
X1 = MCD-00091: Crystal 32.768kHz, 6pF, +-20ppm, 50Kohms max, SMD; Manufacturer_Part_Number: NX3215SA-32.768KHZ-EXS00A-MU00525; Manufacturer: NDK; Part_Type: Crystal_Osc; BMS_Part_Number: 9157034; Part_Preference: Recommended; Provided_By: SUBCO; Component_Country_Of_Origin: Unknown; ID: 2553; ShowFields: YES
X4 = MCD-01036: Crystal 24MHz, 6pF, +-20ppm, 80ohms max, SMD; Part_Type: Crystal_Osc; Manufacturer: NDK; BMS_Part_Number: 9157045; Part_Preference: Recommended; Provided_By: SUBCO; Component_Country_Of_Origin: Unknown; ID: 2989; ShowFields: YES

## Sheet Arduino.SchDoc: Arduino
size A4; Date: Not used; ApprovedBy: Not used; CheckedBy: Not used; Author: Not used; CompanyName: STMicroelectronics; DrawnBy: Not used; Engineer: Not used; Organization: Not used; Address1: Not used; Address2: Not used; Address3: Not used; Address4: Not used; DocumentNumber: Not used; Revision: Not used; SheetNumber: 12; SheetTotal: 17
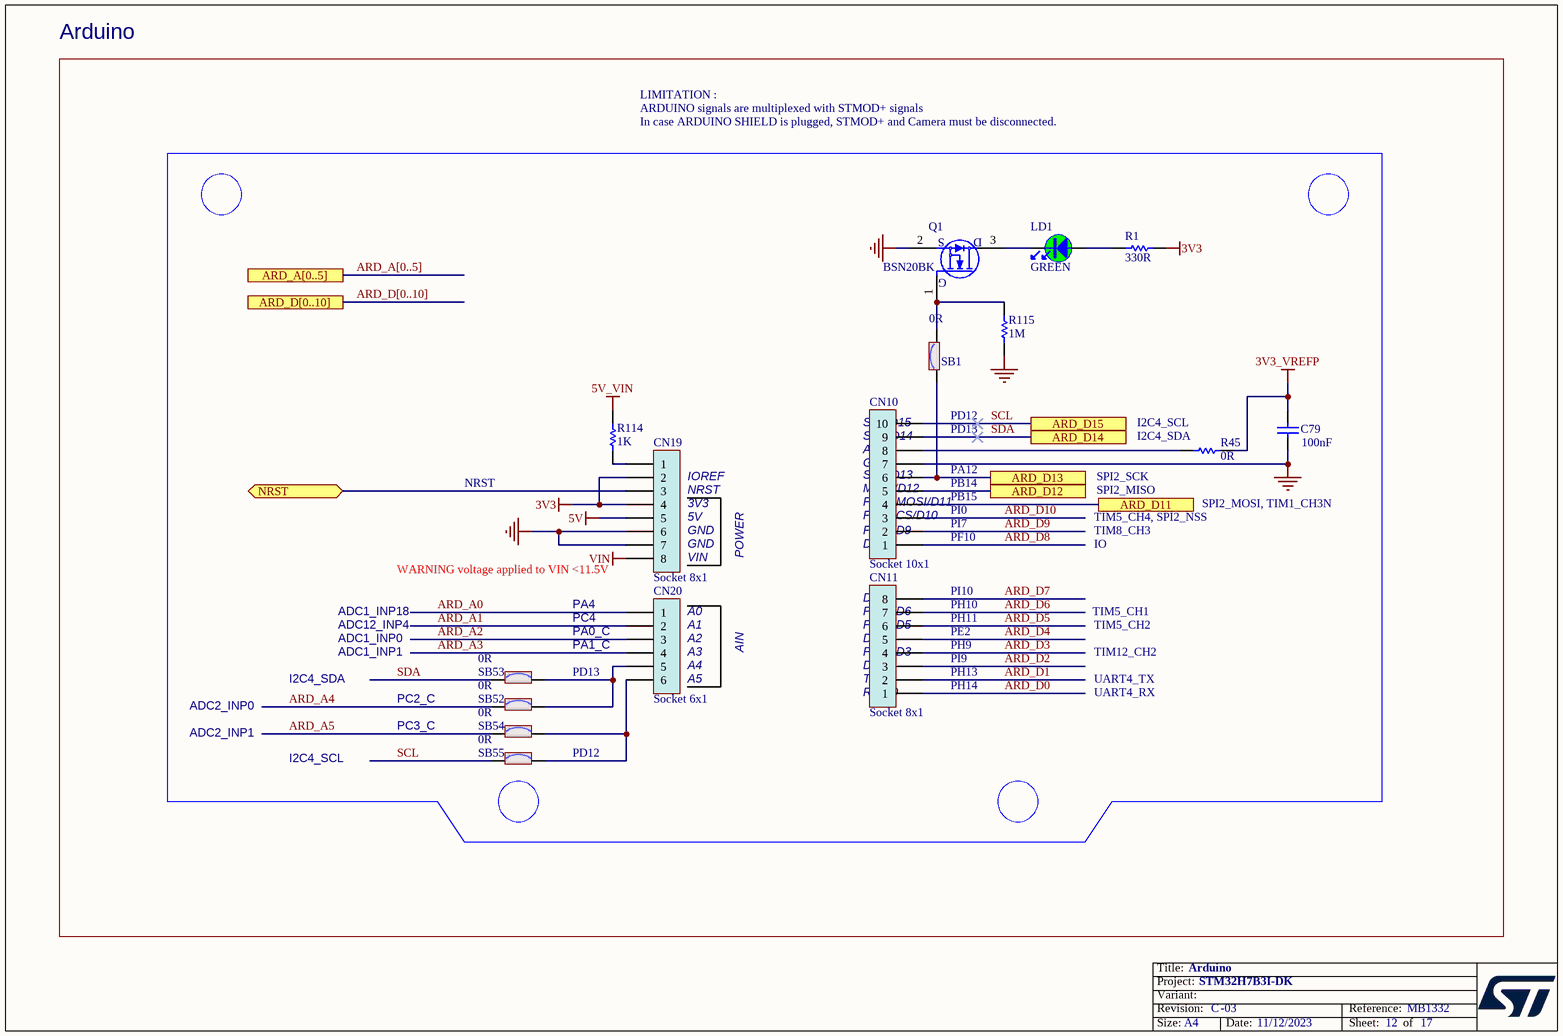
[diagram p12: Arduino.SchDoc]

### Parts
C79  value 100nF  [C0402]  (hidden comment: Capacitor)
CN10  Socket 10x1  [CON_FISCHER_BL1-10-G]
CN11  Socket 8x1  [CON_FISCHER_BL1-8-G]
CN19  Socket 8x1  [CON_FISCHER_BL1-8-G]
CN20  Socket 6x1  [CON_FISCHER_BL1-6-G]
LD1  value GREEN  [LED_0603_OSRAM_LG-Q396-PS-35_GREEN_1A2K_H0P4]  (hidden comment: LED_green)
Q1  value BSN20BK  [MOS_SOT23]  (hidden comment: BSN20)
R1  value 330R  [R0402]  (hidden comment: Resistor)
R45  value 0R  [R0402]  (hidden comment: Resistor)
R114  value 1K  [R0402]  (hidden comment: Resistor)
R115  value 1M  [R0402]  (hidden comment: Resistor)
SB1  value 0R  [SOLDER-BRIDGE_R0603-0R]  (hidden comment: SB_ON)
SB52  value 0R  [SOLDER-BRIDGE_R0603-0R]  (hidden comment: SB_ON)
SB53  value 0R  [SOLDER-BRIDGE_R0603-0R]  (hidden comment: SB_ON)
SB54  value 0R  [SOLDER-BRIDGE_R0603-0R]  (hidden comment: SB_ON)
SB55  value 0R  [SOLDER-BRIDGE_R0603-0R]  (hidden comment: SB_ON)

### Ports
ARD_A[0..5], ARD_D11, ARD_D12, ARD_D13, ARD_D14, ARD_D15, ARD_D[0..10], NRST (bidir)

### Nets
3V3: CN19.2 CN19.4 R1.2
3V3_VREFP: C79.1 R45.2
5V: CN19.5
5V_VIN: R114.2
GND: C79.2 CN10.7 CN19.6 CN19.7 Q1.2(S) R115.1
VIN: CN19.8
ARD_A0: CN20.1
ARD_A1: CN20.2
ARD_A2: CN20.3
ARD_A3: CN20.4
ARD_A4: SB52.1
ARD_A5: SB54.1
ARD_D0: CN11.1
ARD_D1: CN11.2
ARD_D2: CN11.3
ARD_D3: CN11.4
ARD_D4: CN11.5
ARD_D5: CN11.6
ARD_D6: CN11.7
ARD_D7: CN11.8
ARD_D8: CN10.1
ARD_D9: CN10.2
ARD_D10: CN10.3
ARD_D11: CN10.4 ; port ARD_D11
ARD_D12: CN10.5 ; port ARD_D12
ARD_D13: CN10.6 SB1.1 ; port ARD_D13
SCL: CN10.10 SB55.1 ; port ARD_D15
SDA: CN10.9 SB53.1 ; port ARD_D14
T_NRST: CN19.3 ; port NRST
NetCN10_8: CN10.8 R45.1
NetCN19_1: CN19.1 R114.1
NetCN20_5: CN20.5 SB52.2 SB53.2
NetCN20_6: CN20.6 SB54.2 SB55.2
NetLD1_1: LD1.1 R1.1
NetLD1_2: LD1.2 Q1.3(D)
NetQ1_1: Q1.1(G) R115.2 SB1.2

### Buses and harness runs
bus ARD_A[0..5] = port ARD_A[0..5]
bus ARD_D[0..10] = port ARD_D[0..10]

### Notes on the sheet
- Arduino
- LIMITATION :
  ARDUINO signals are multiplexed with STMOD+ signals
  In case ARDUINO SHIELD is plugged, STMOD+ and Camera must be disconnected.
- (near CN10) SDA/D14
- (near CN10) SCL/D15
- PD12
- PD13
- (near R45) I2C4_SCL
- (near R45) I2C4_SDA
- NRST
- (near CN19) IOREF
- (near CN19) NRST
- (near CN19) 3V3
- (near CN19) 5V
- (near CN10) PWM/CS/D10
- (near CN10) SCK/D13
- (near CN10) MISO/D12
- (near CN10) PWM/MOSI/D11
- (near CN10) AVDD
- (near CN10) GND
- PI0
- PA12
- PB14
- PB15
- TIM5_CH4, SPI2_NSS
- (near R45) SPI2_SCK
- SPI2_MISO
- SPI2_MOSI, TIM1_CH3N
- WARNING voltage applied to VIN <11.5V
- (near CN19) GND
- (near CN19) VIN
- POWER
- (near CN10) D8
- (near CN10) PWM/D9
- PF10
- PI7
- TIM8_CH3
- IO
- ADC1_INP0
- ADC1_INP1
- ADC1_INP18
- ADC12_INP4
- PA1_C
- PA0_C
- PC4
- PA4
- (near CN20) A0
- (near CN20) A1
- (near CN20) A2
- (near CN20) A3
- AIN
- (near CN11) D4
- (near CN11) PWM/D3
- (near CN11) PWM/D5
- (near CN11) PWM/D6
- (near CN11) D7
- PH9
- PH10
- PE2
- PI10
- PH11
- TIM5_CH1
- TIM5_CH2
- TIM12_CH2
- ADC2_INP0
- I2C4_SDA
- PC2_C
- (near CN20) A4
- (near CN20) A5
- (near CN11) RX/D0
- (near CN11) TX/D1
- (near CN11) D2
- PI9
- PH14
- PH13
- UART4_TX
- UART4_RX
- ADC2_INP1
- I2C4_SCL
- PC3_C

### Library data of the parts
C79 = MCD-00006: as C90 on sheet Peripherals
CN10 = MCD-00024: Socket, 10x1, 2.54mm, VR, TH, Height 8mm/3.3mm; Part_Type: Connector; Manufacturer_Part_Number: BL 1-10 G; Manufacturer: FISCHER ELECTRONIK; Alternate_Manufacturer_Part_Number: 218110S1610; Alternate_Manufacturer: JIUBABA; Part_Preference: Recommended; Provided_By: SUBCO; Component_Country_Of_Origin: Germany; ID: 2491; ShowFields: YES
CN11 CN19 = MCD-00025: Socket, 8x1, 2.54mm, VR, TH, Height 8mm/3.3mm; Part_Type: Connector; Manufacturer_Part_Number: BL 1-8 G; Manufacturer: FISCHER ELECTRONIK; Alternate_Manufacturer_Part_Number: 218108S1610; Alternate_Manufacturer: JIUBABA; Part_Preference: Recommended; Provided_By: SUBCO; Component_Country_Of_Origin: Germany; ID: 2490; ShowFields: YES
CN20 = MCD-00026: Socket, 6x1, 2.54mm, VR, TH, Height 8mm/3.3mm; Part_Type: Connector; Manufacturer_Part_Number: BL 1-6 G; Manufacturer: FISCHER ELECTRONIK; Alternate_Manufacturer_Part_Number: 218106S1610; Alternate_Manufacturer: JIUBABA; Part_Preference: Recommended; Provided_By: SUBCO; Component_Country_Of_Origin: Germany; ID: 2493; ShowFields: YES
LD1 = MCD-00588: as LD6 on sheet USB_OTG_HS_externalPHY
Q1 = MCD-01969: Transistor, N-channel enhancement mode field-effect transistor; Part_Preference: Recommended; Manufacturer: NEXPERIA; Order_Code_RS: 136-4845; Component_Country_Of_Origin: China; ID: 4069; ShowFields: YES
R1 = MCD-00062: Resistor,330R,0402,1%,1/16W; Manufacturer_Part_Number: RC0402FR-07330RL; Manufacturer: YAGEO; Part_Preference: Recommended; Provided_By: SUBCO; Component_Country_Of_Origin: China; ID: 2529; Order_Code_RS: 9239170; ShowFields: YES
R45 = MCD-00052: as R62 on sheet MCU
R114 = MCD-00061: Resistor,1K,0402,1%,1/16W; Manufacturer_Part_Number: RC0402FR-071KL; Manufacturer: YAGEO; Part_Preference: Recommended; Provided_By: SUBCO; Component_Country_Of_Origin: China; ID: 2532; Order_Code_RS: 9239235; ShowFields: YES
R115 = MCD-00182: Resistor,1M,0402,1%,1/16W; Manufacturer_Part_Number: RC0402FR-071ML; Manufacturer: YAGEO; BMS_Part_Number: 9131778; Part_Preference: Recommended; Provided_By: SUBCO; Component_Country_Of_Origin: China; ID: 2686; Order_Code_RS: 618-6194; ShowFields: YES
SB1 SB52-SB55 = MCD-00071: as SB6-SB19 on sheet Peripherals

## Sheet JTAG.SchDoc: JTAG
size A4; Date: Not used; ApprovedBy: Not used; CheckedBy: Not used; Author: Not used; CompanyName: STMicroelectronics; DrawnBy: Not used; Engineer: Not used; Organization: Not used; Address1: Not used; Address2: Not used; Address3: Not used; Address4: Not used; DocumentNumber: Not used; Revision: Not used; SheetNumber: 16; SheetTotal: 17
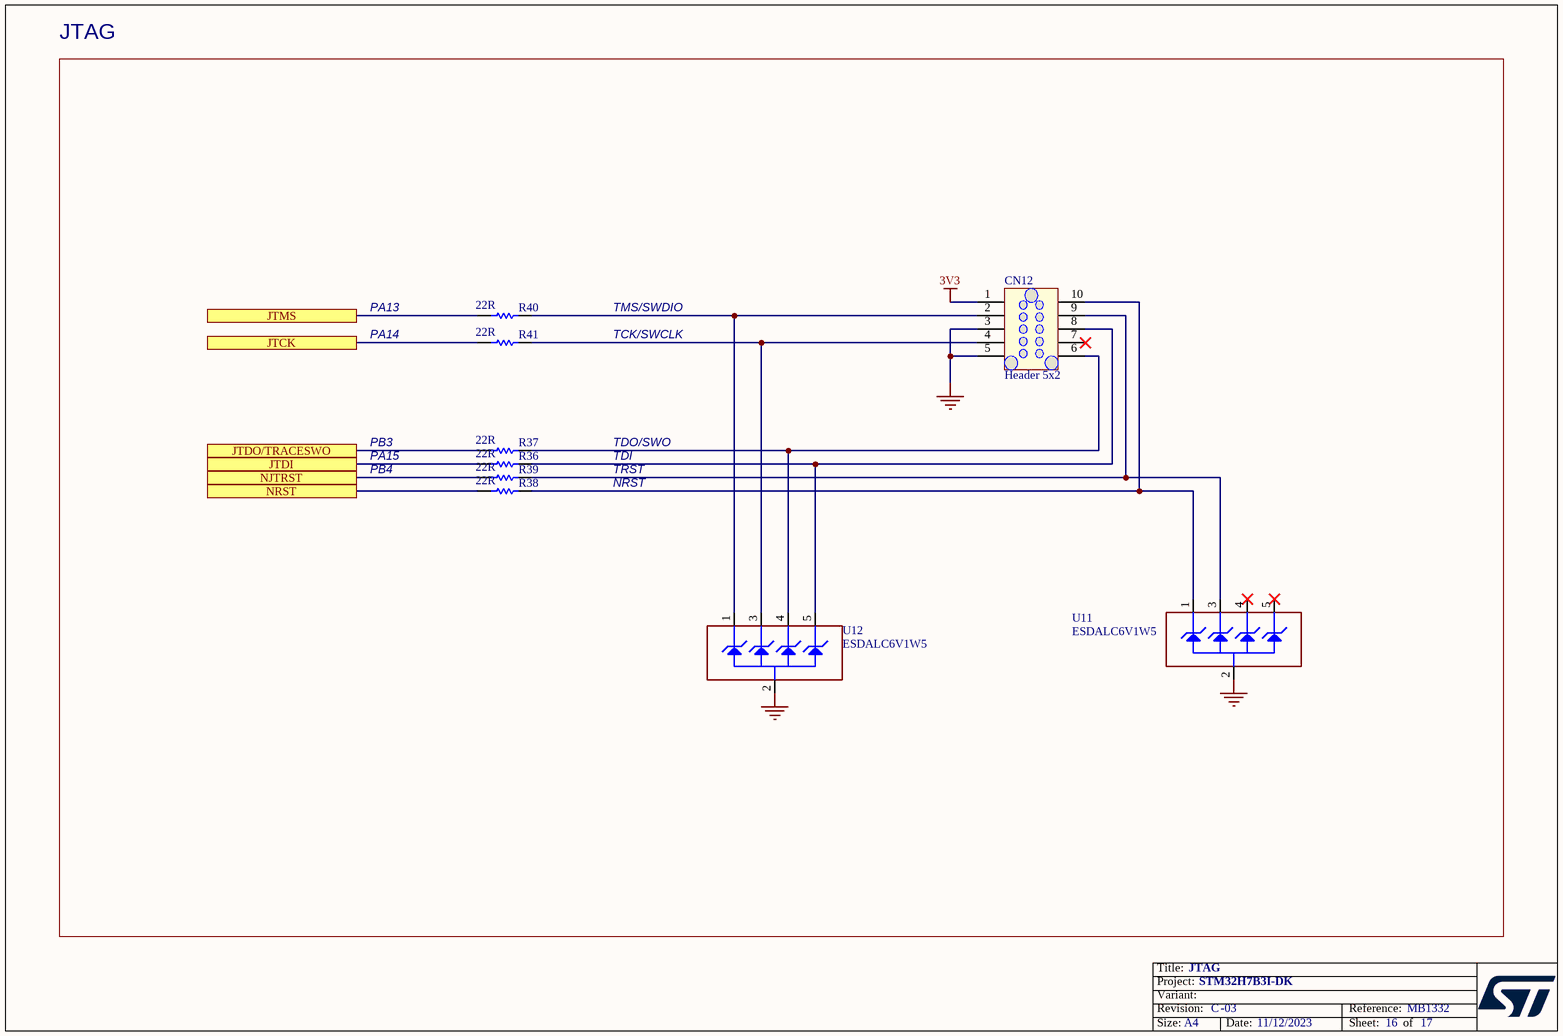
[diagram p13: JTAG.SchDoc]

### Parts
CN12  value Header 5x2  [CON_TAG-C_TC2050-IDC-NL]  (hidden comment: Tag-10-C)
R36  value 22R  [R0603]  (hidden comment: Resistor)
R37  value 22R  [R0603]  (hidden comment: Resistor)
R38  value 22R  [R0603]  (hidden comment: Resistor)
R39  value 22R  [R0603]  (hidden comment: Resistor)
R40  value 22R  [R0603]  (hidden comment: Resistor)
R41  value 22R  [R0603]  (hidden comment: Resistor)
U11  ESDALC6V1W5  [ESD_SOT323-5L]
U12  ESDALC6V1W5  [ESD_SOT323-5L]

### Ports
JTCK, JTDI, JTDO/TRACESWO, JTMS, NJTRST, NRST

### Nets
3V3: CN12.1
GND: CN12.3 CN12.5 U11.2(GND) U12.2(GND)
JTDI: R36.2 ; port JTDI
NJTRST: R39.2 ; port NJTRST
T_NRST: R38.2 ; port NRST
T_SWCLK: R41.2 ; port JTCK
T_SWDIO: R40.2 ; port JTMS
T_SWO: R37.2 ; port JTDO/TRACESWO
NetCN12_2: CN12.2 R40.1 U12.1(IO1)
NetCN12_4: CN12.4 R41.1 U12.3(IO2)
NetCN12_6: CN12.6 R37.1 U12.4(IO3)
NetCN12_8: CN12.8 R36.1 U12.5(IO4)
NetCN12_9: CN12.9 R39.1 U11.3(IO2)
NetCN12_10: CN12.10 R38.1 U11.1(IO1)

Not connected (* = marked no-connect by the designer): CN12 7*; U11 4(IO3)* 5(IO4)*

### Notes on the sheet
- JTAG
- PA13
- TMS/SWDIO
- PA14
- TCK/SWCLK
- PB3
- TDO/SWO
- PA15
- PB4
- TDI
- TRST
- NRST

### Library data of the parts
CN12 = MCD-00031: Tag_Connector Header, 10x2, No legs; Part_Preference: Recommended; Provided_By: SUBCO; ID: 2486; ShowFields: YES
R36-R41 = MCD-00066: Resistor,22R,0603,1%,1/10W; Manufacturer_Part_Number: RC0603FR-0722RL; Manufacturer: YAGEO; Part_Preference: Recommended; Provided_By: SUBCO; Component_Country_Of_Origin: China; ID: 2530; Order_Code_RS: 9238280; ShowFields: YES
U11 U12 = MCD-00136: Dual Transil array for ESD protection; Part_Type: Diode; Manufacturer: STMICROELECTRONICS; BMS_Part_Number: 9151112; Manufacturer_HQ_COO: EU; Part_Preference: Recommended; Provided_By: SUBCO with ST control; Component_Country_Of_Origin: China; ID: 2731; Order_Code_RS: 178-7373; ShowFields: YES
